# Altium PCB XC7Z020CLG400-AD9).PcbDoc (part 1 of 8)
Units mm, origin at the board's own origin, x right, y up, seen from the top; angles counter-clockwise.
Board outline 38 x 38 mm, 14 copper layers (Top Layer, GND02, ART03, PWR04, ART05, GND06, ART07, ART08, PWR09, ART10, GND11, ART12, PWR13, Bottom Layer); 276 components, 302 nets, 1684 pads, 1576 vias.
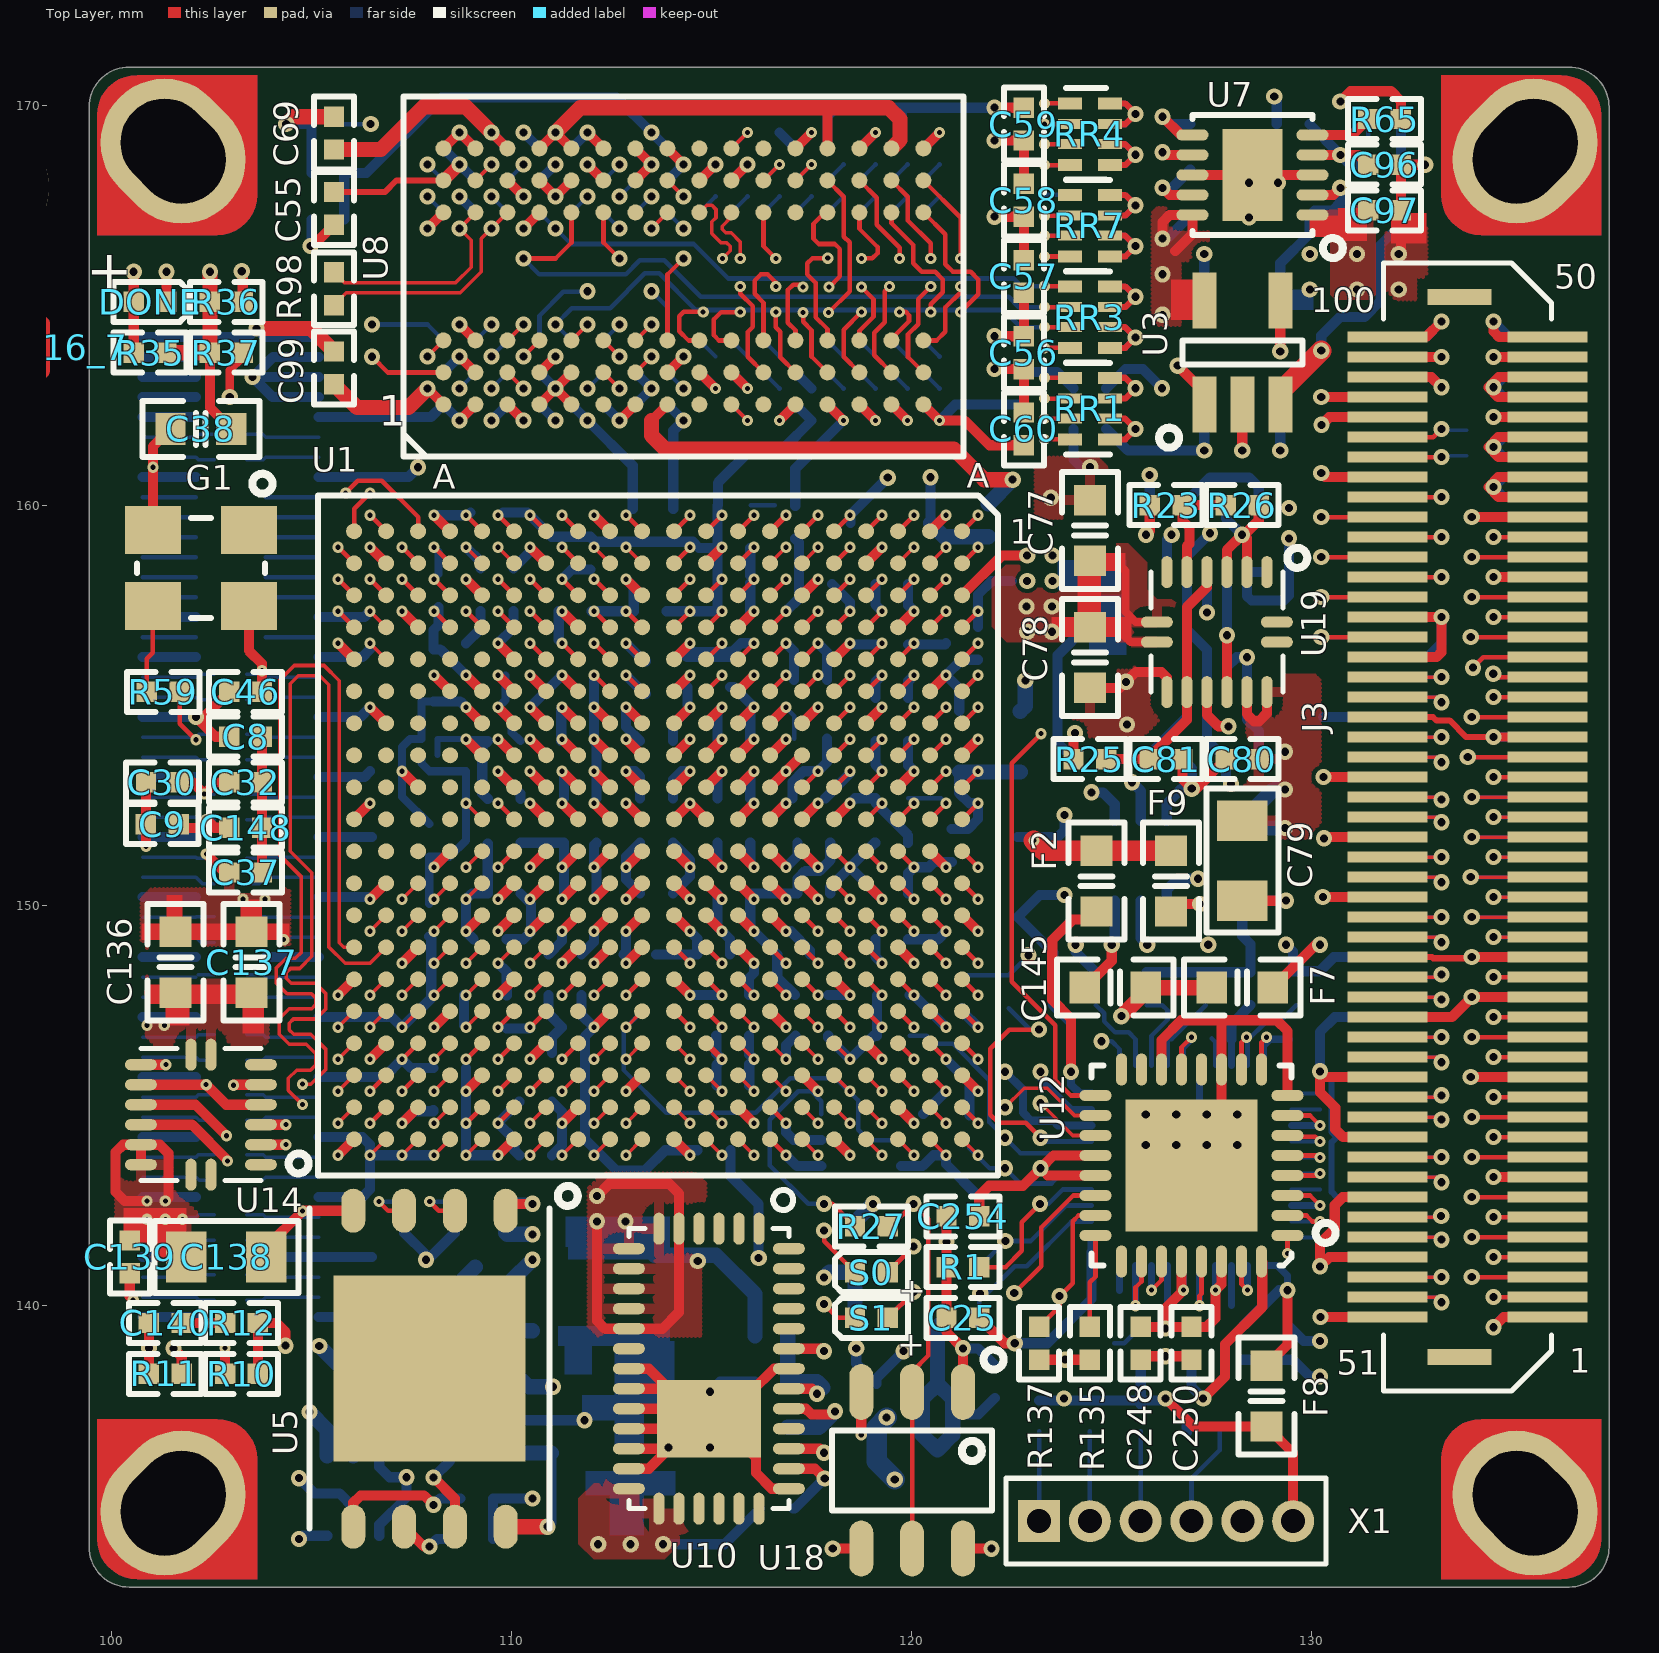
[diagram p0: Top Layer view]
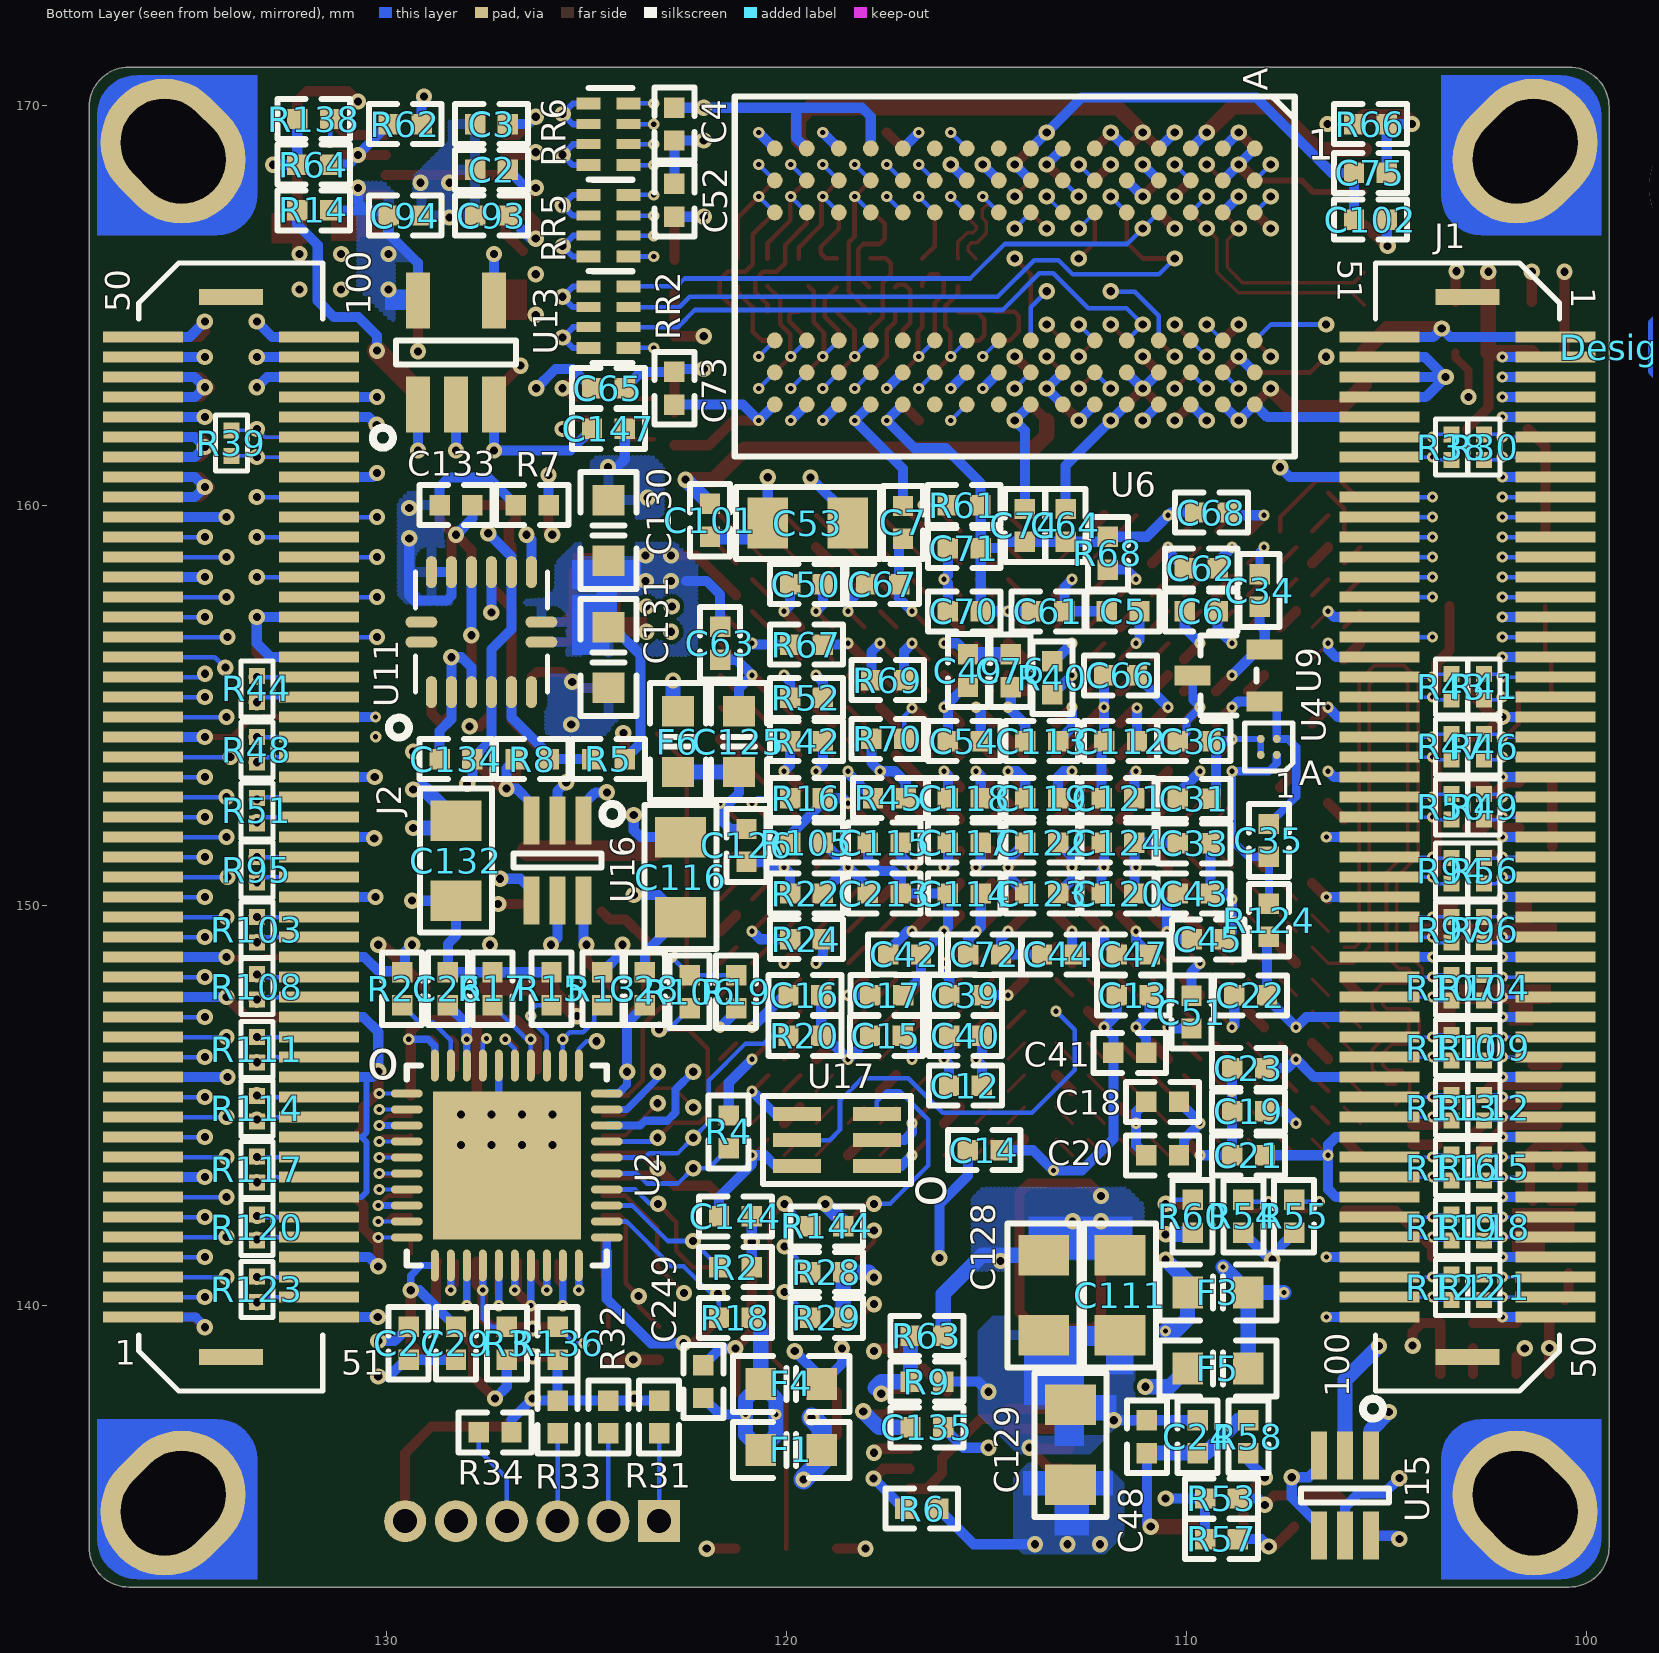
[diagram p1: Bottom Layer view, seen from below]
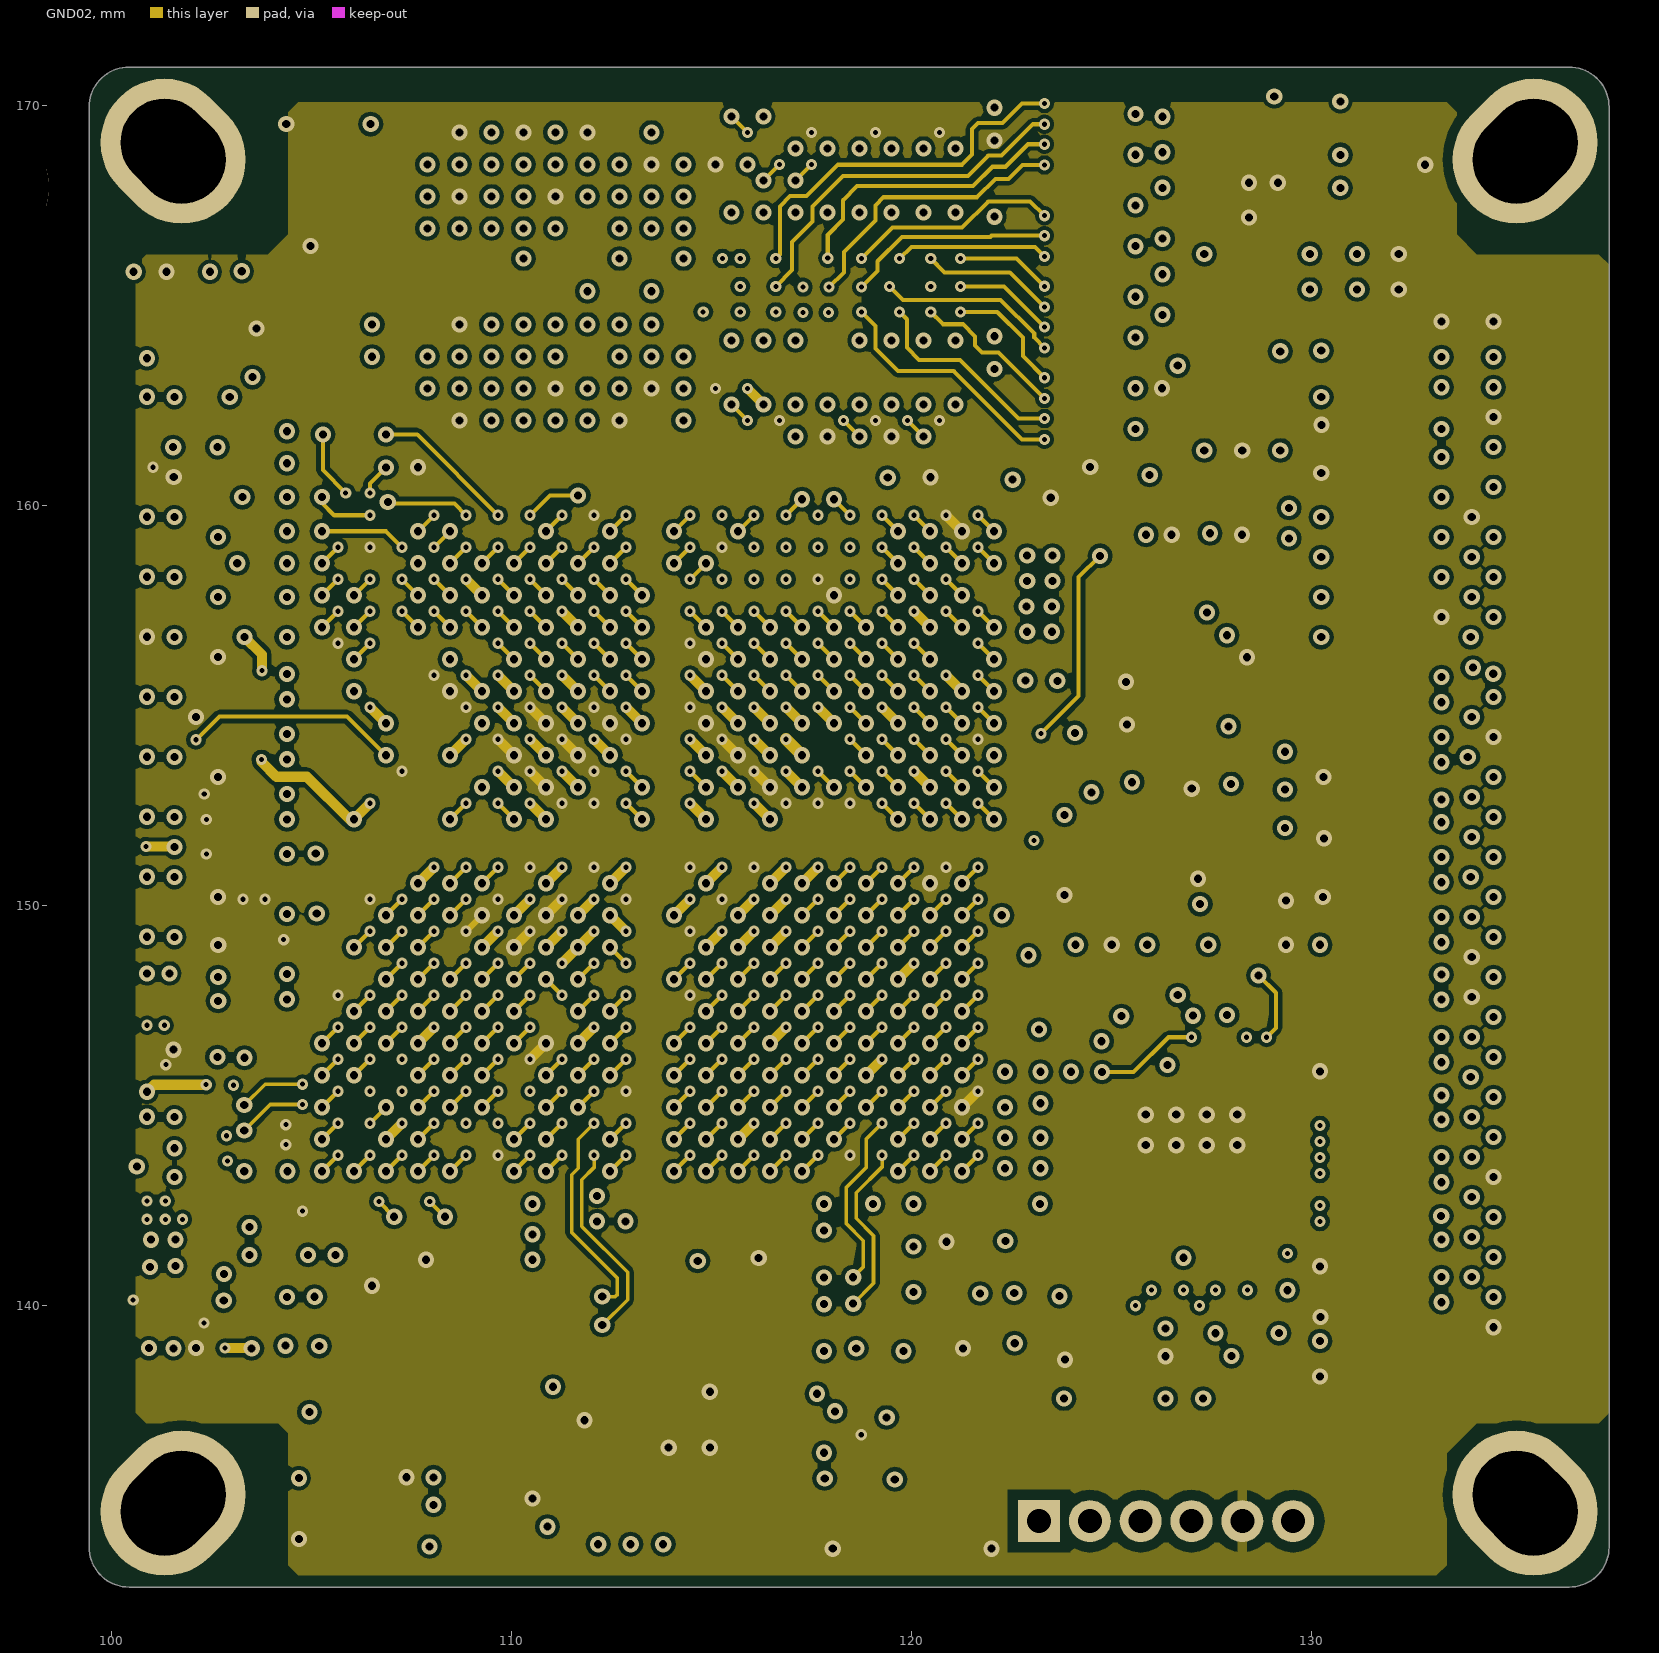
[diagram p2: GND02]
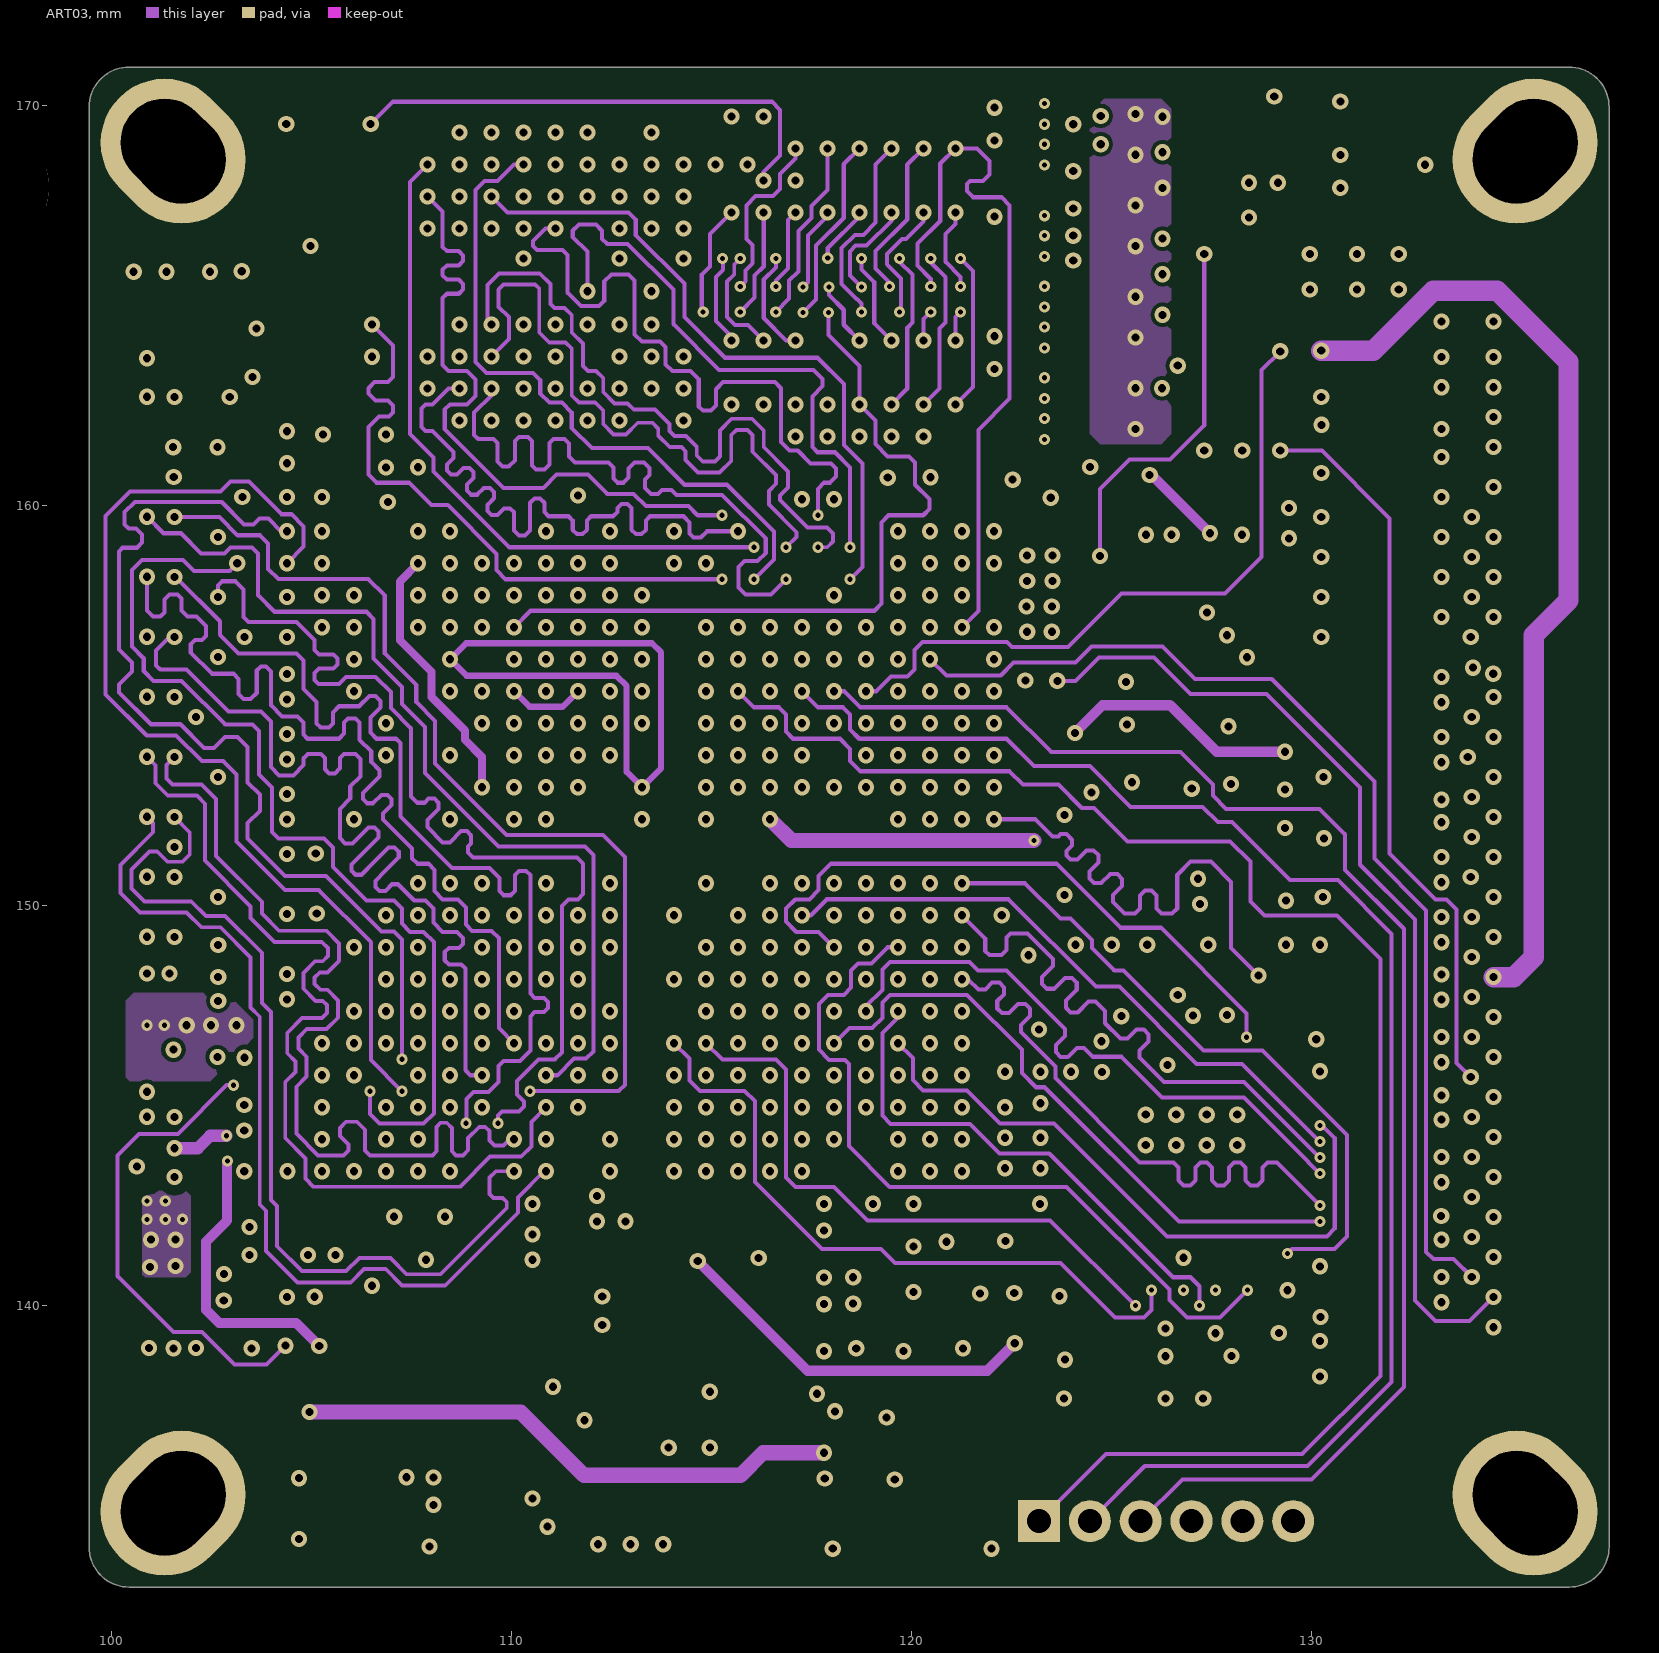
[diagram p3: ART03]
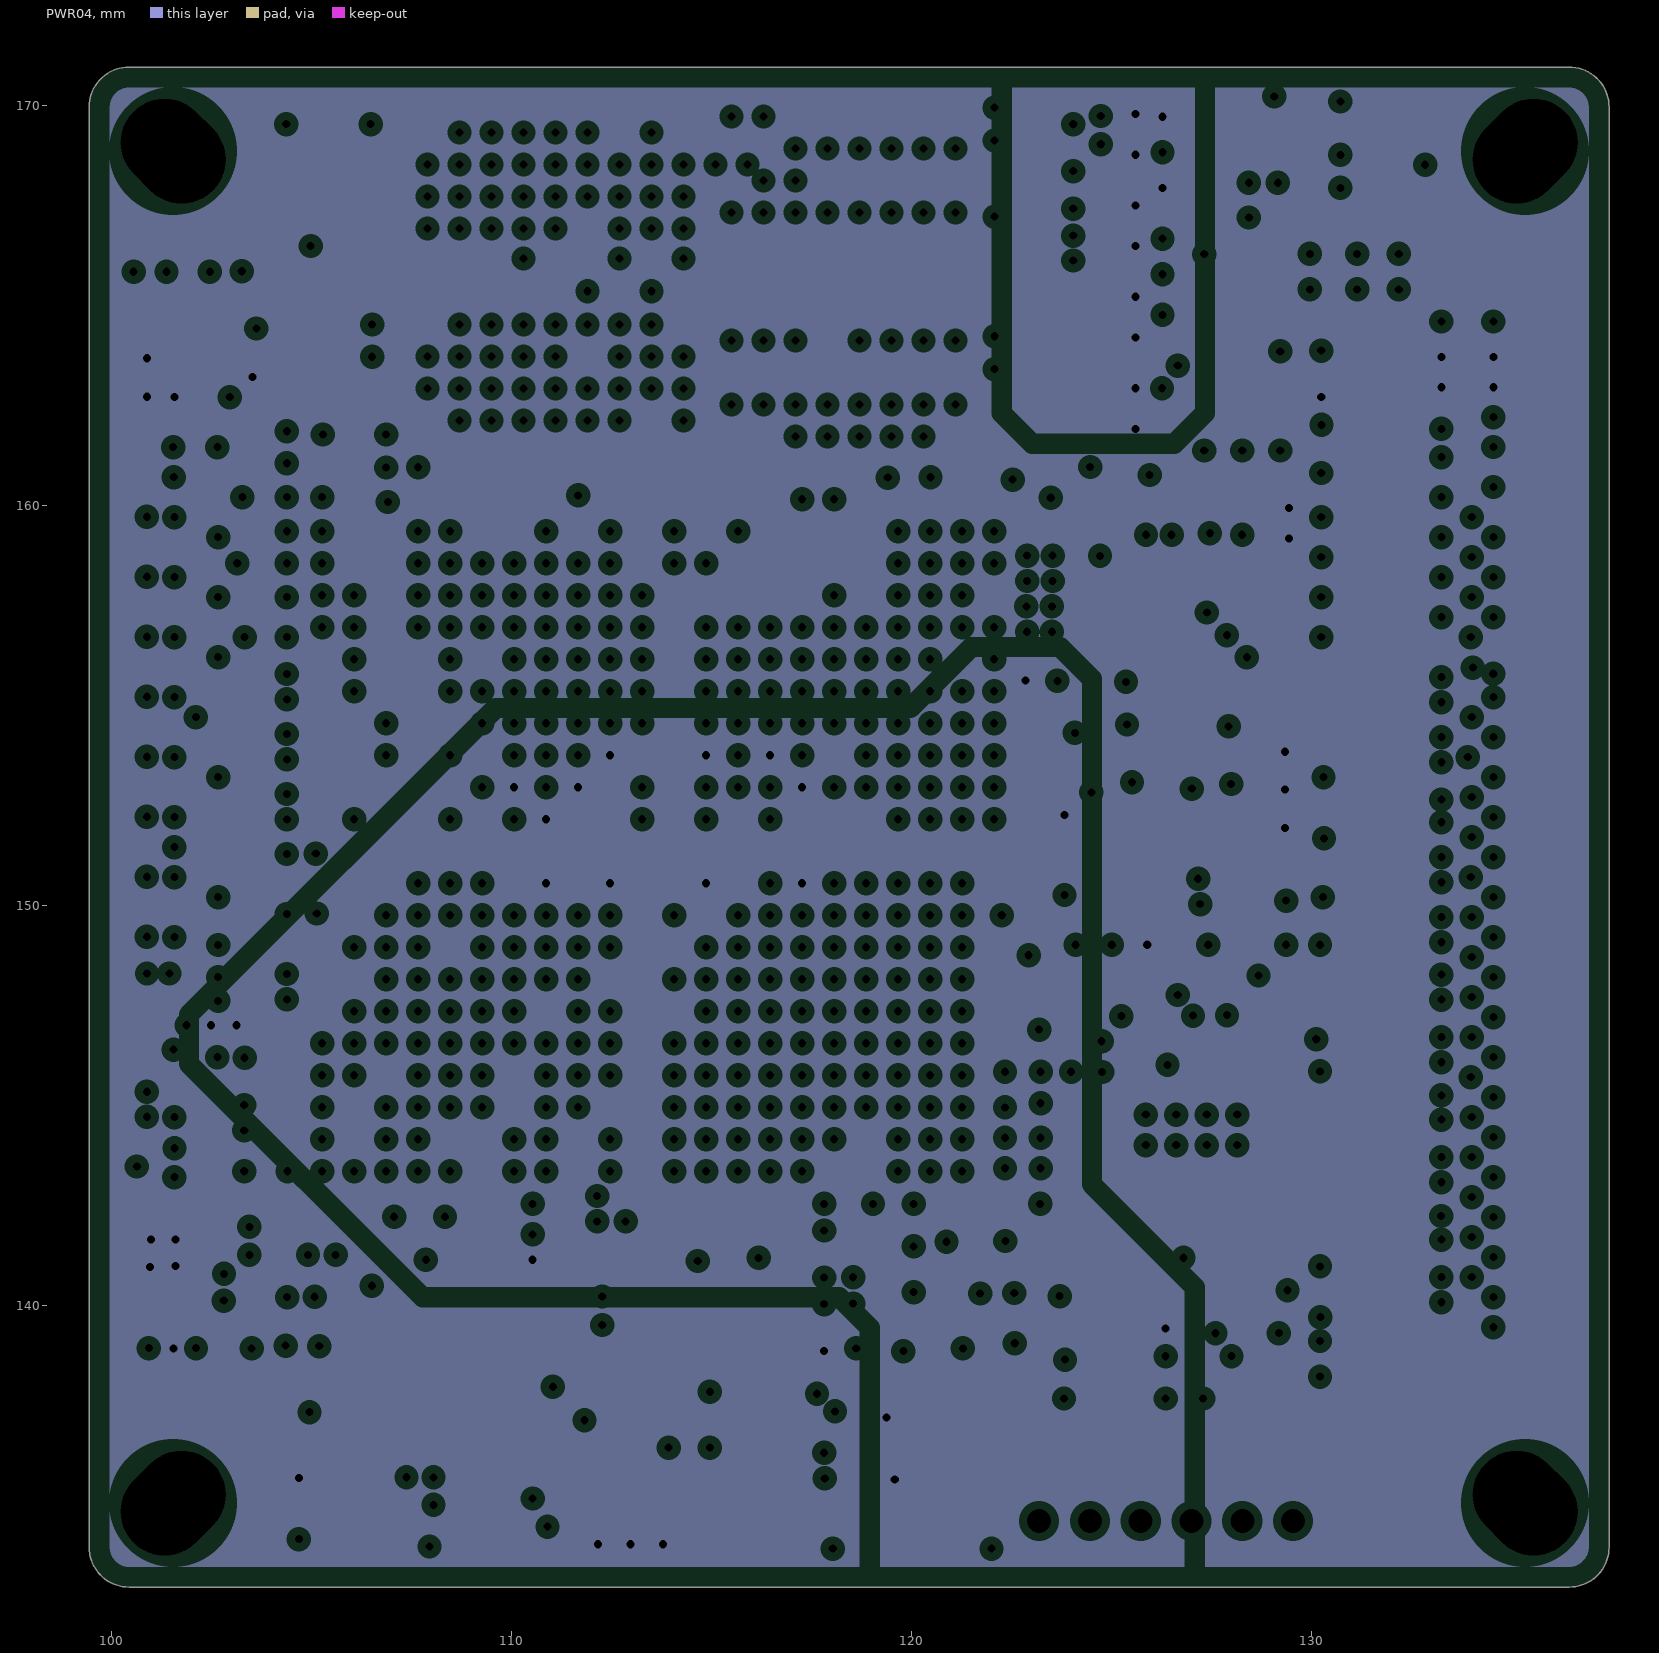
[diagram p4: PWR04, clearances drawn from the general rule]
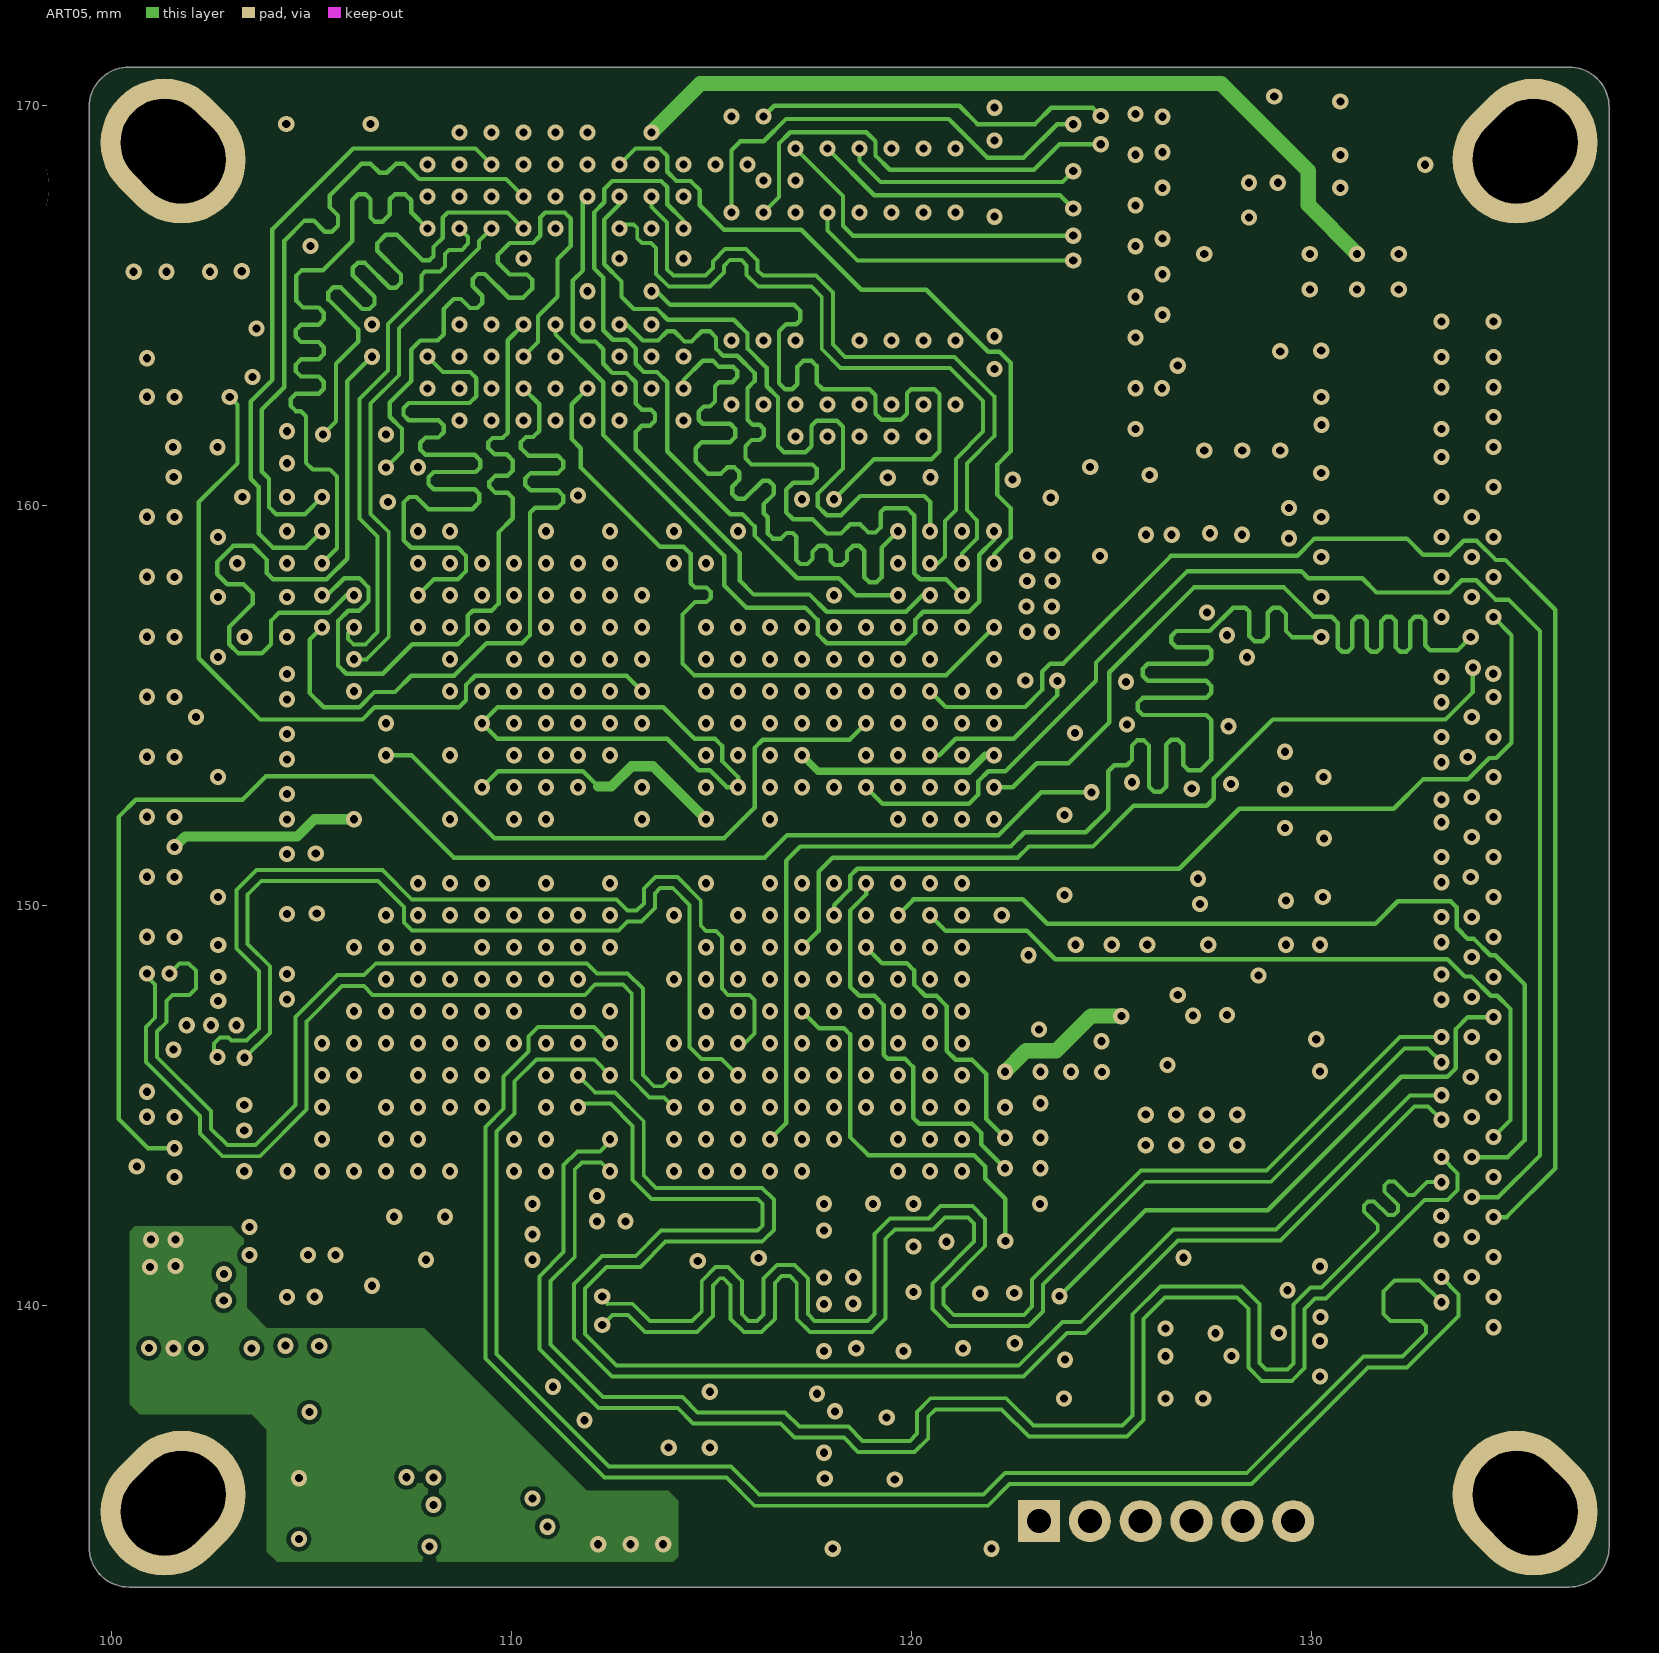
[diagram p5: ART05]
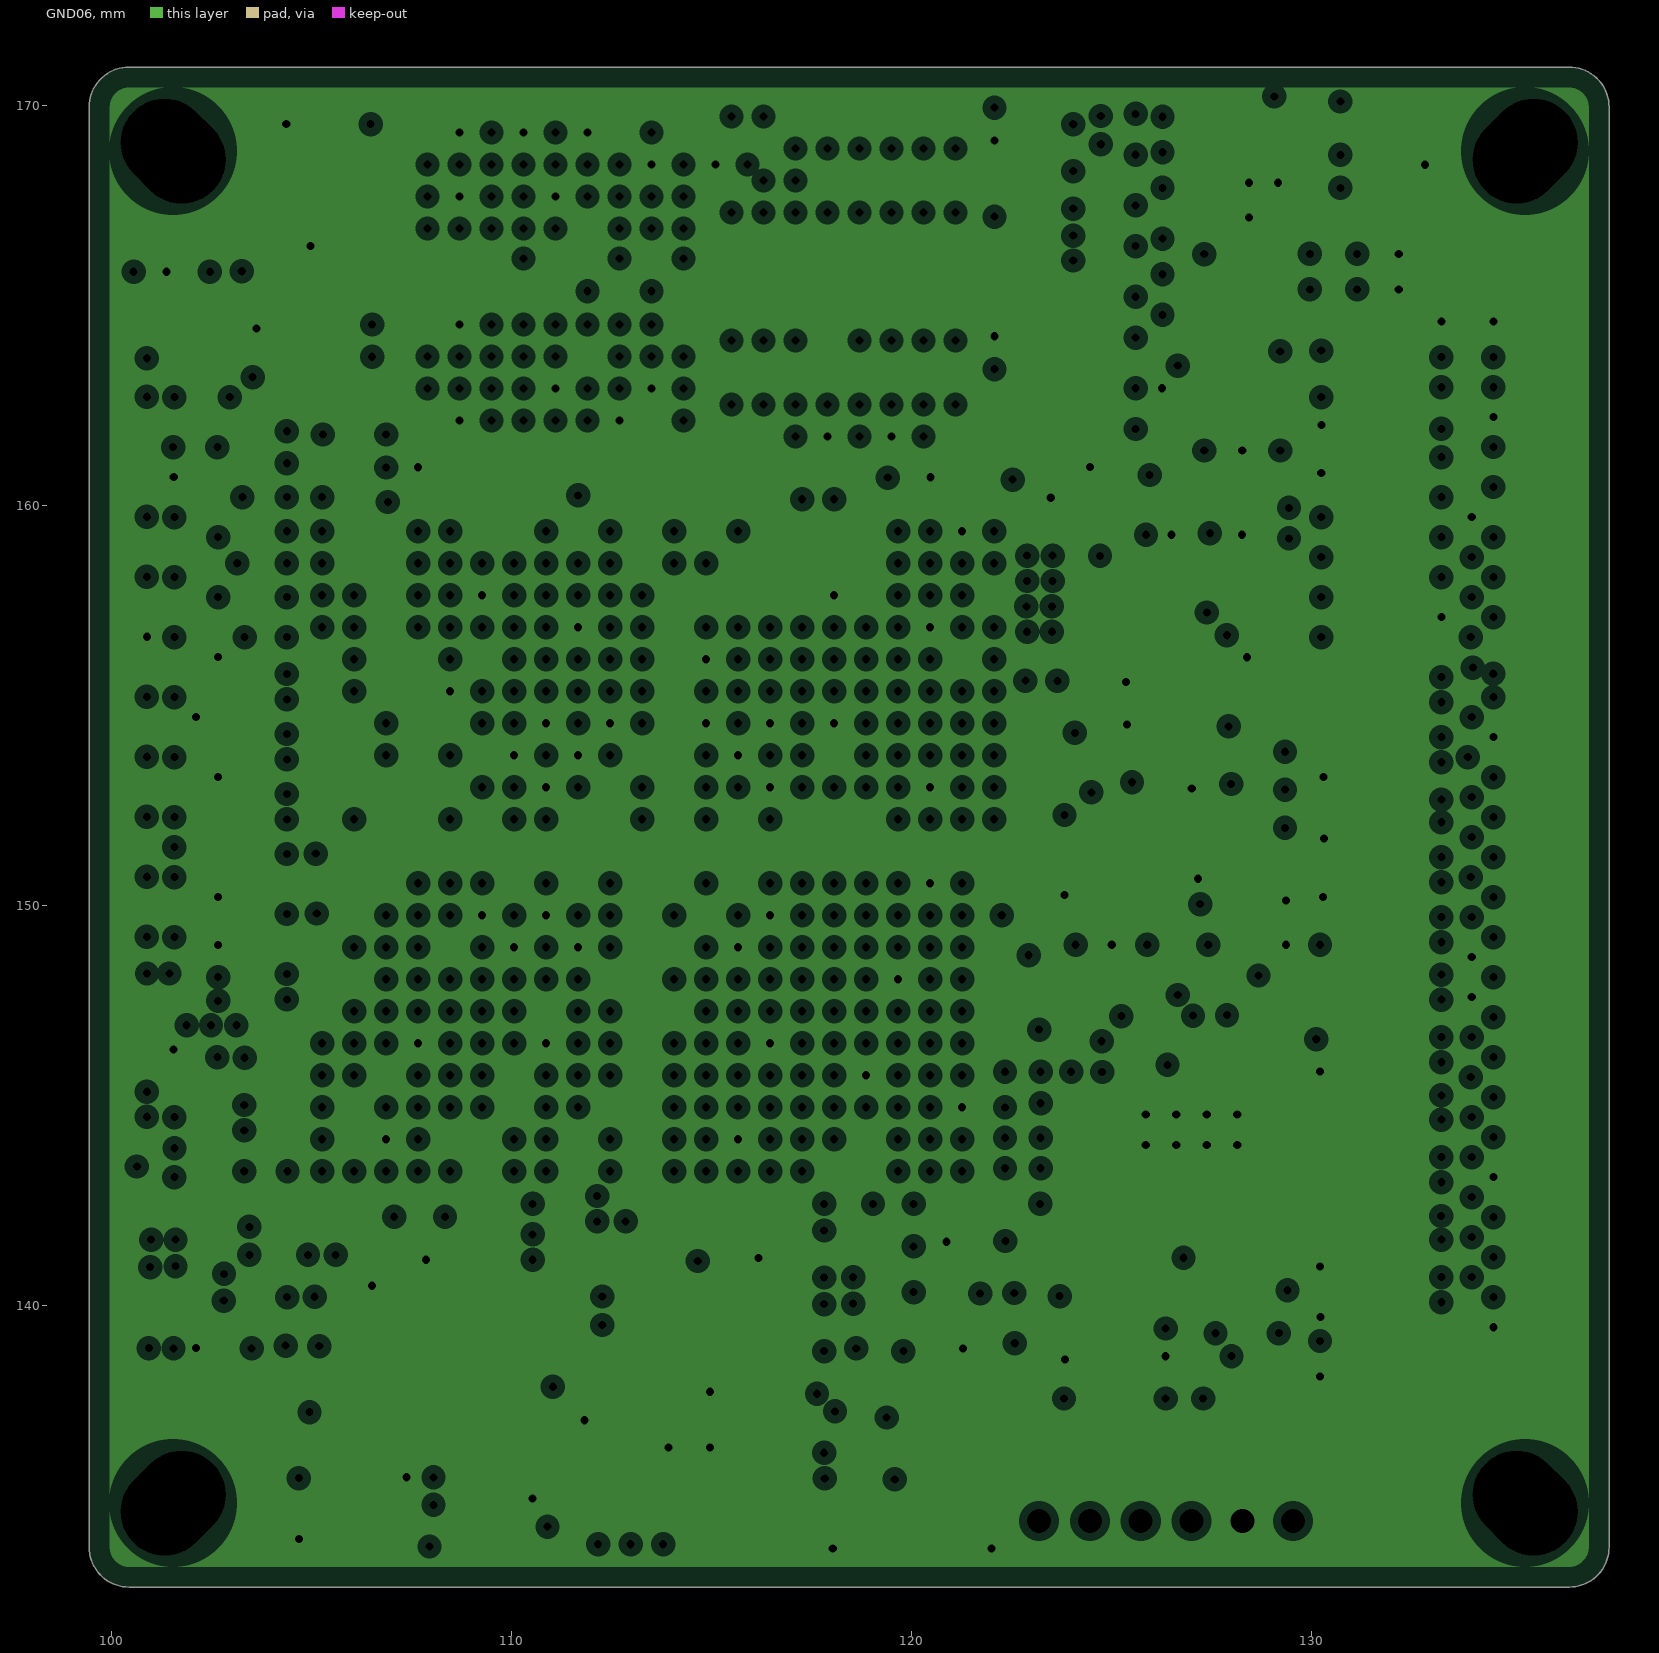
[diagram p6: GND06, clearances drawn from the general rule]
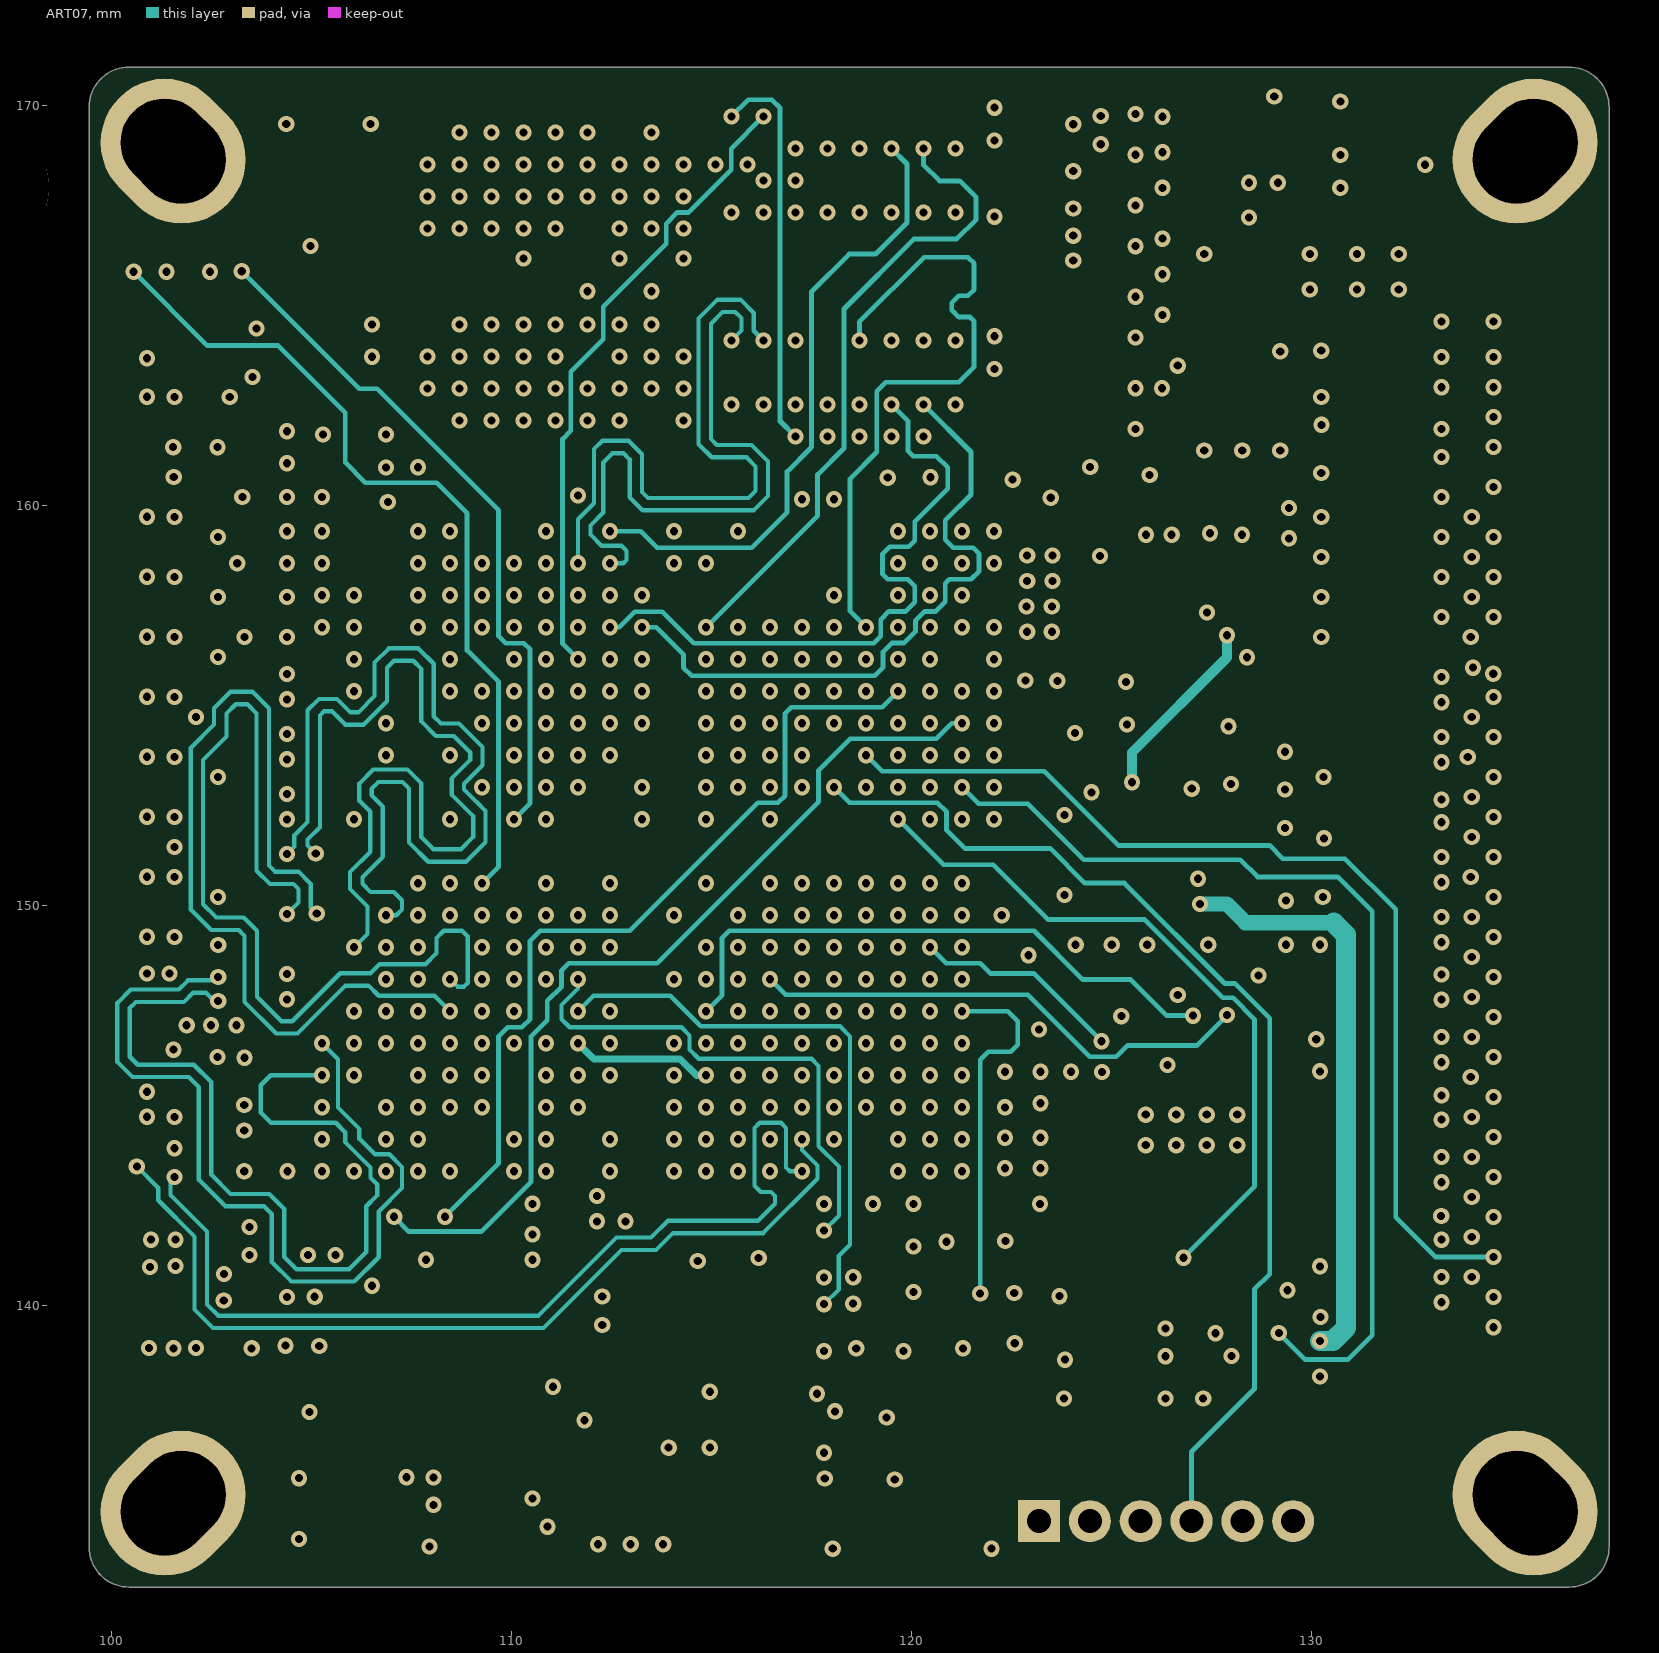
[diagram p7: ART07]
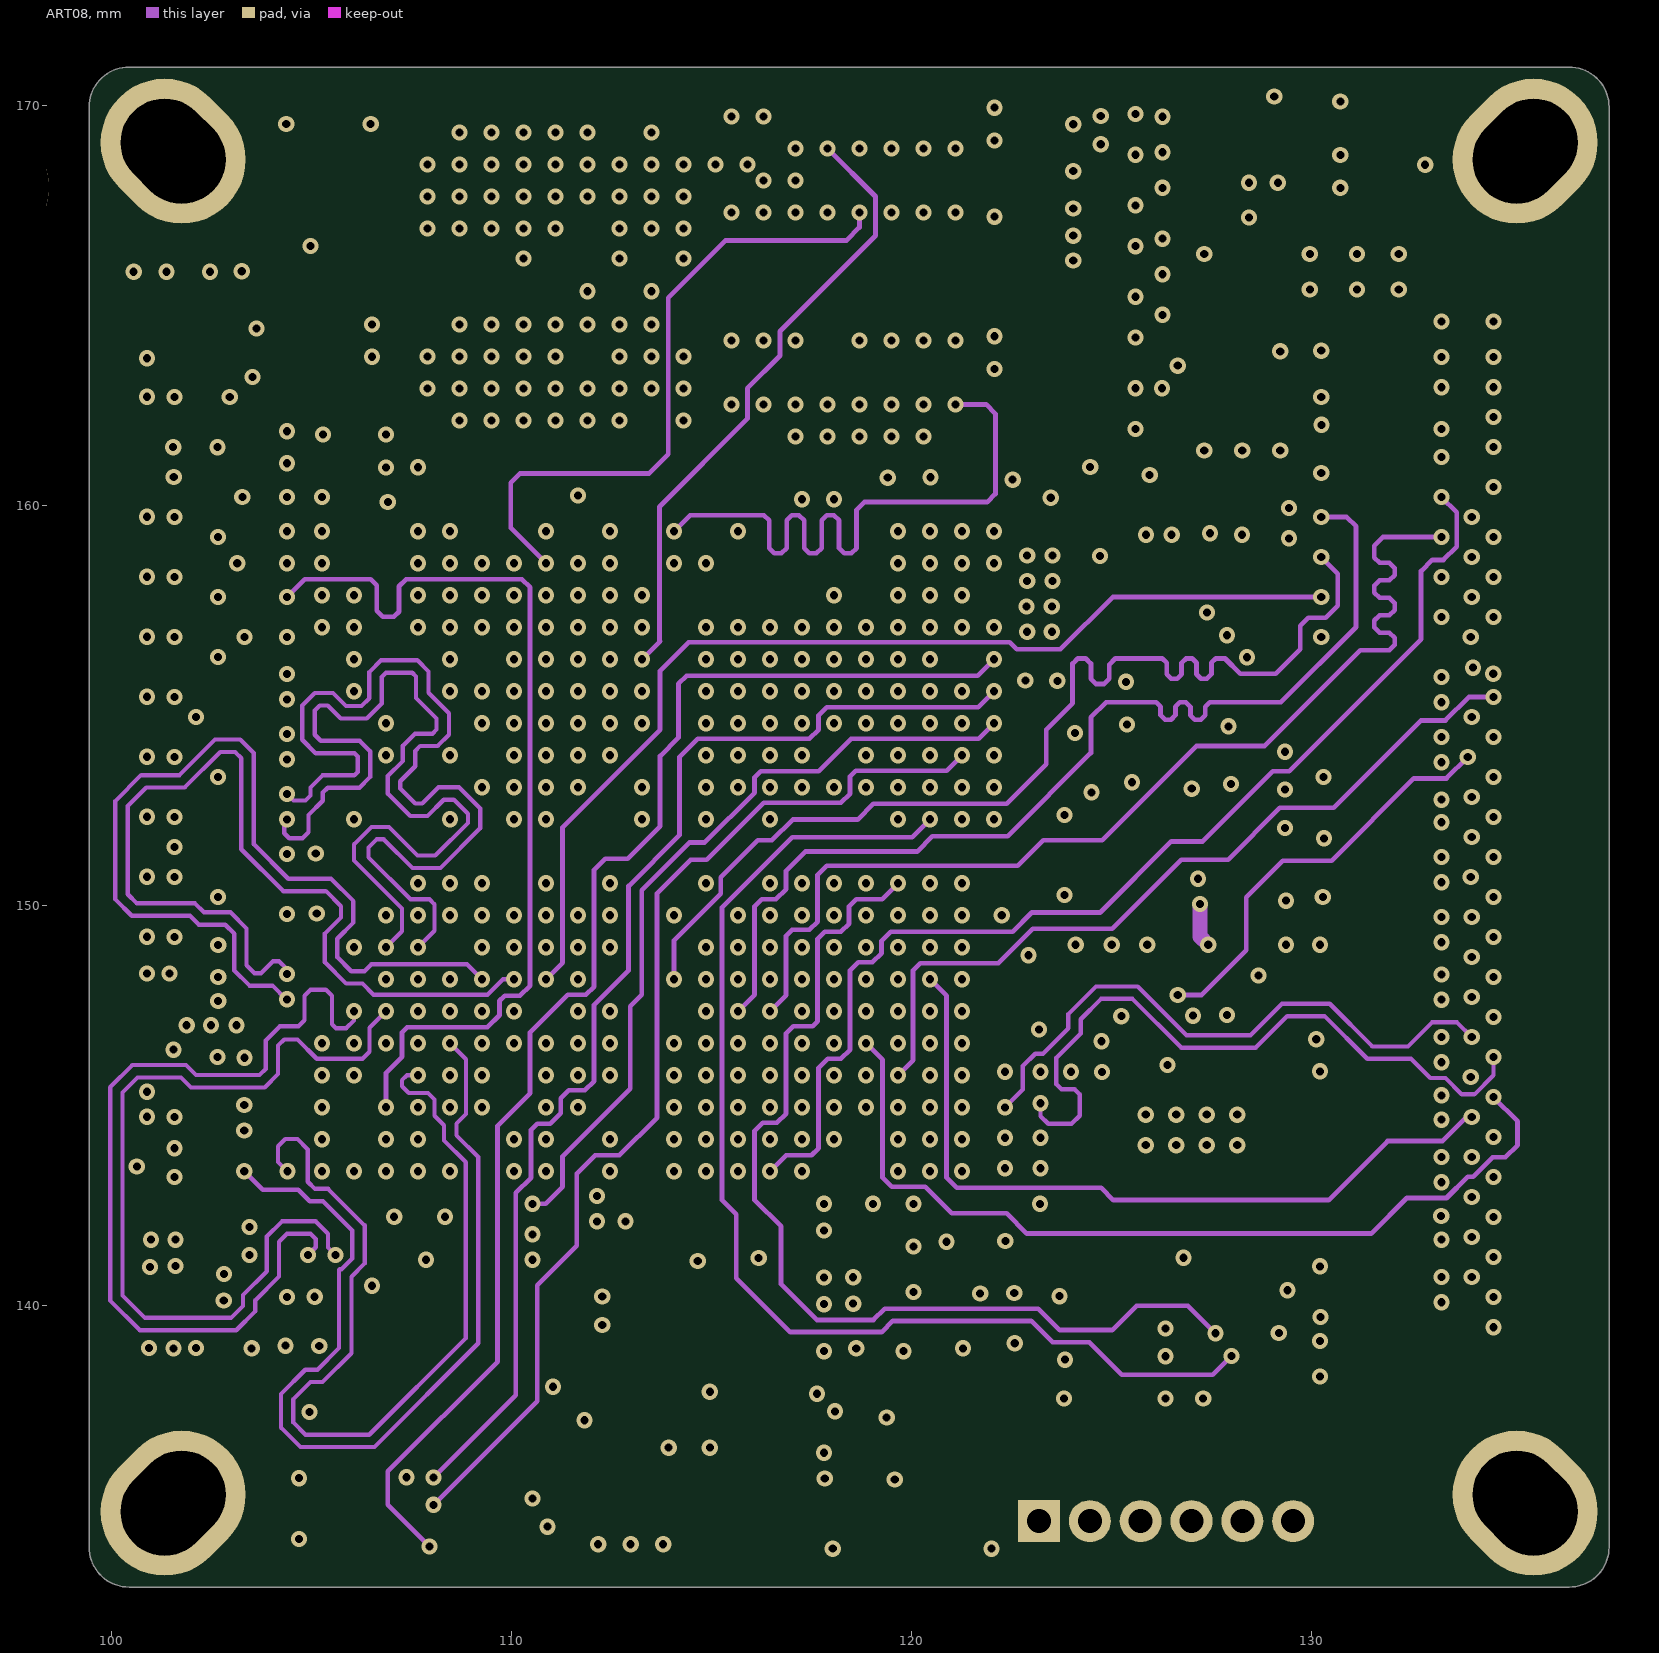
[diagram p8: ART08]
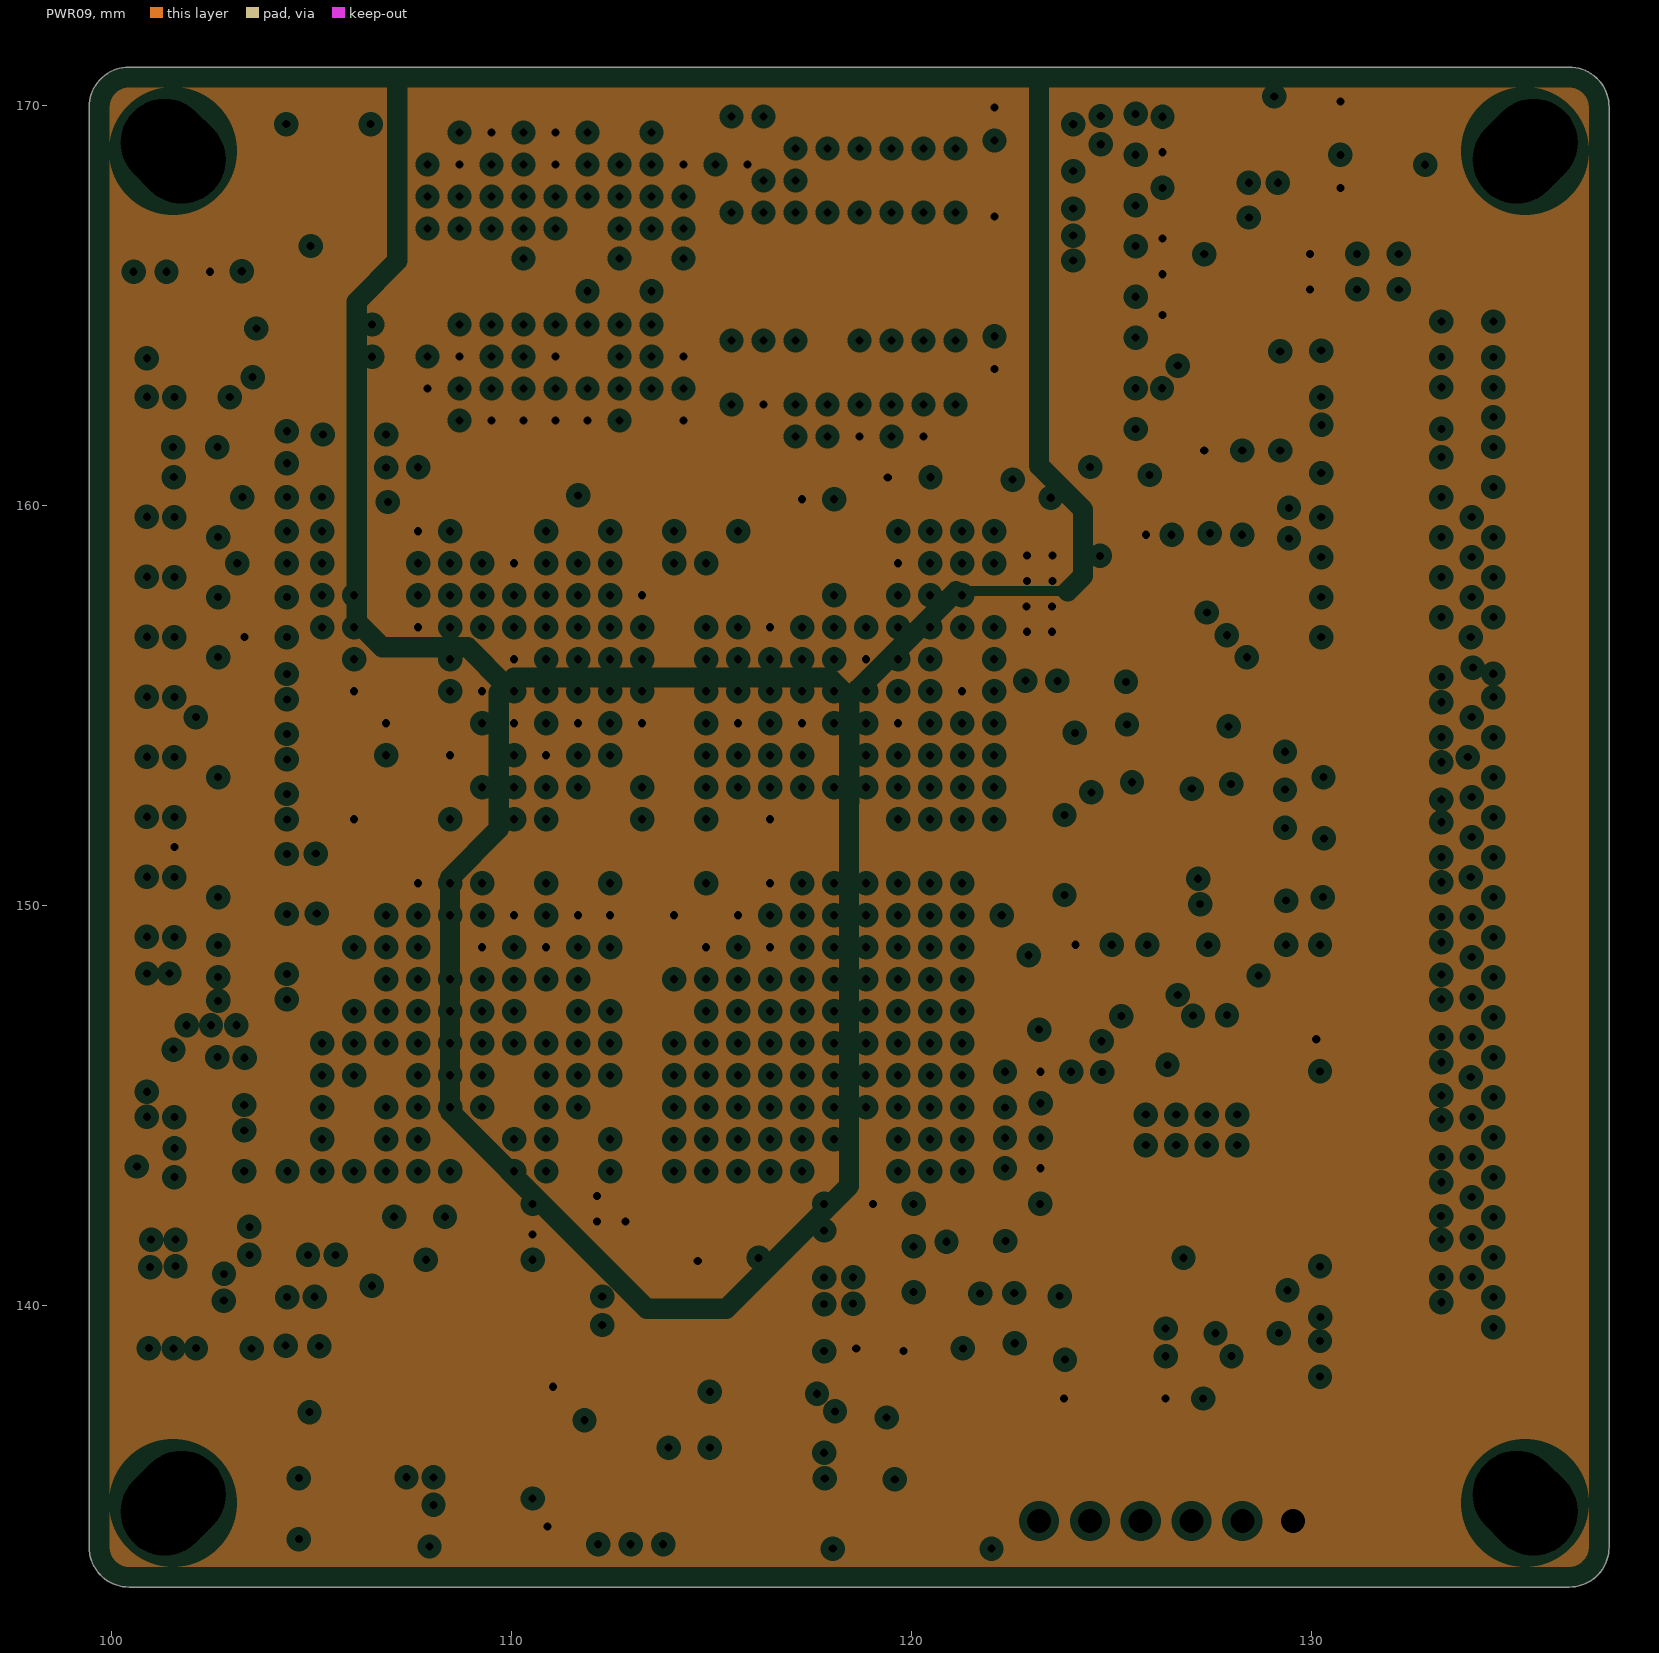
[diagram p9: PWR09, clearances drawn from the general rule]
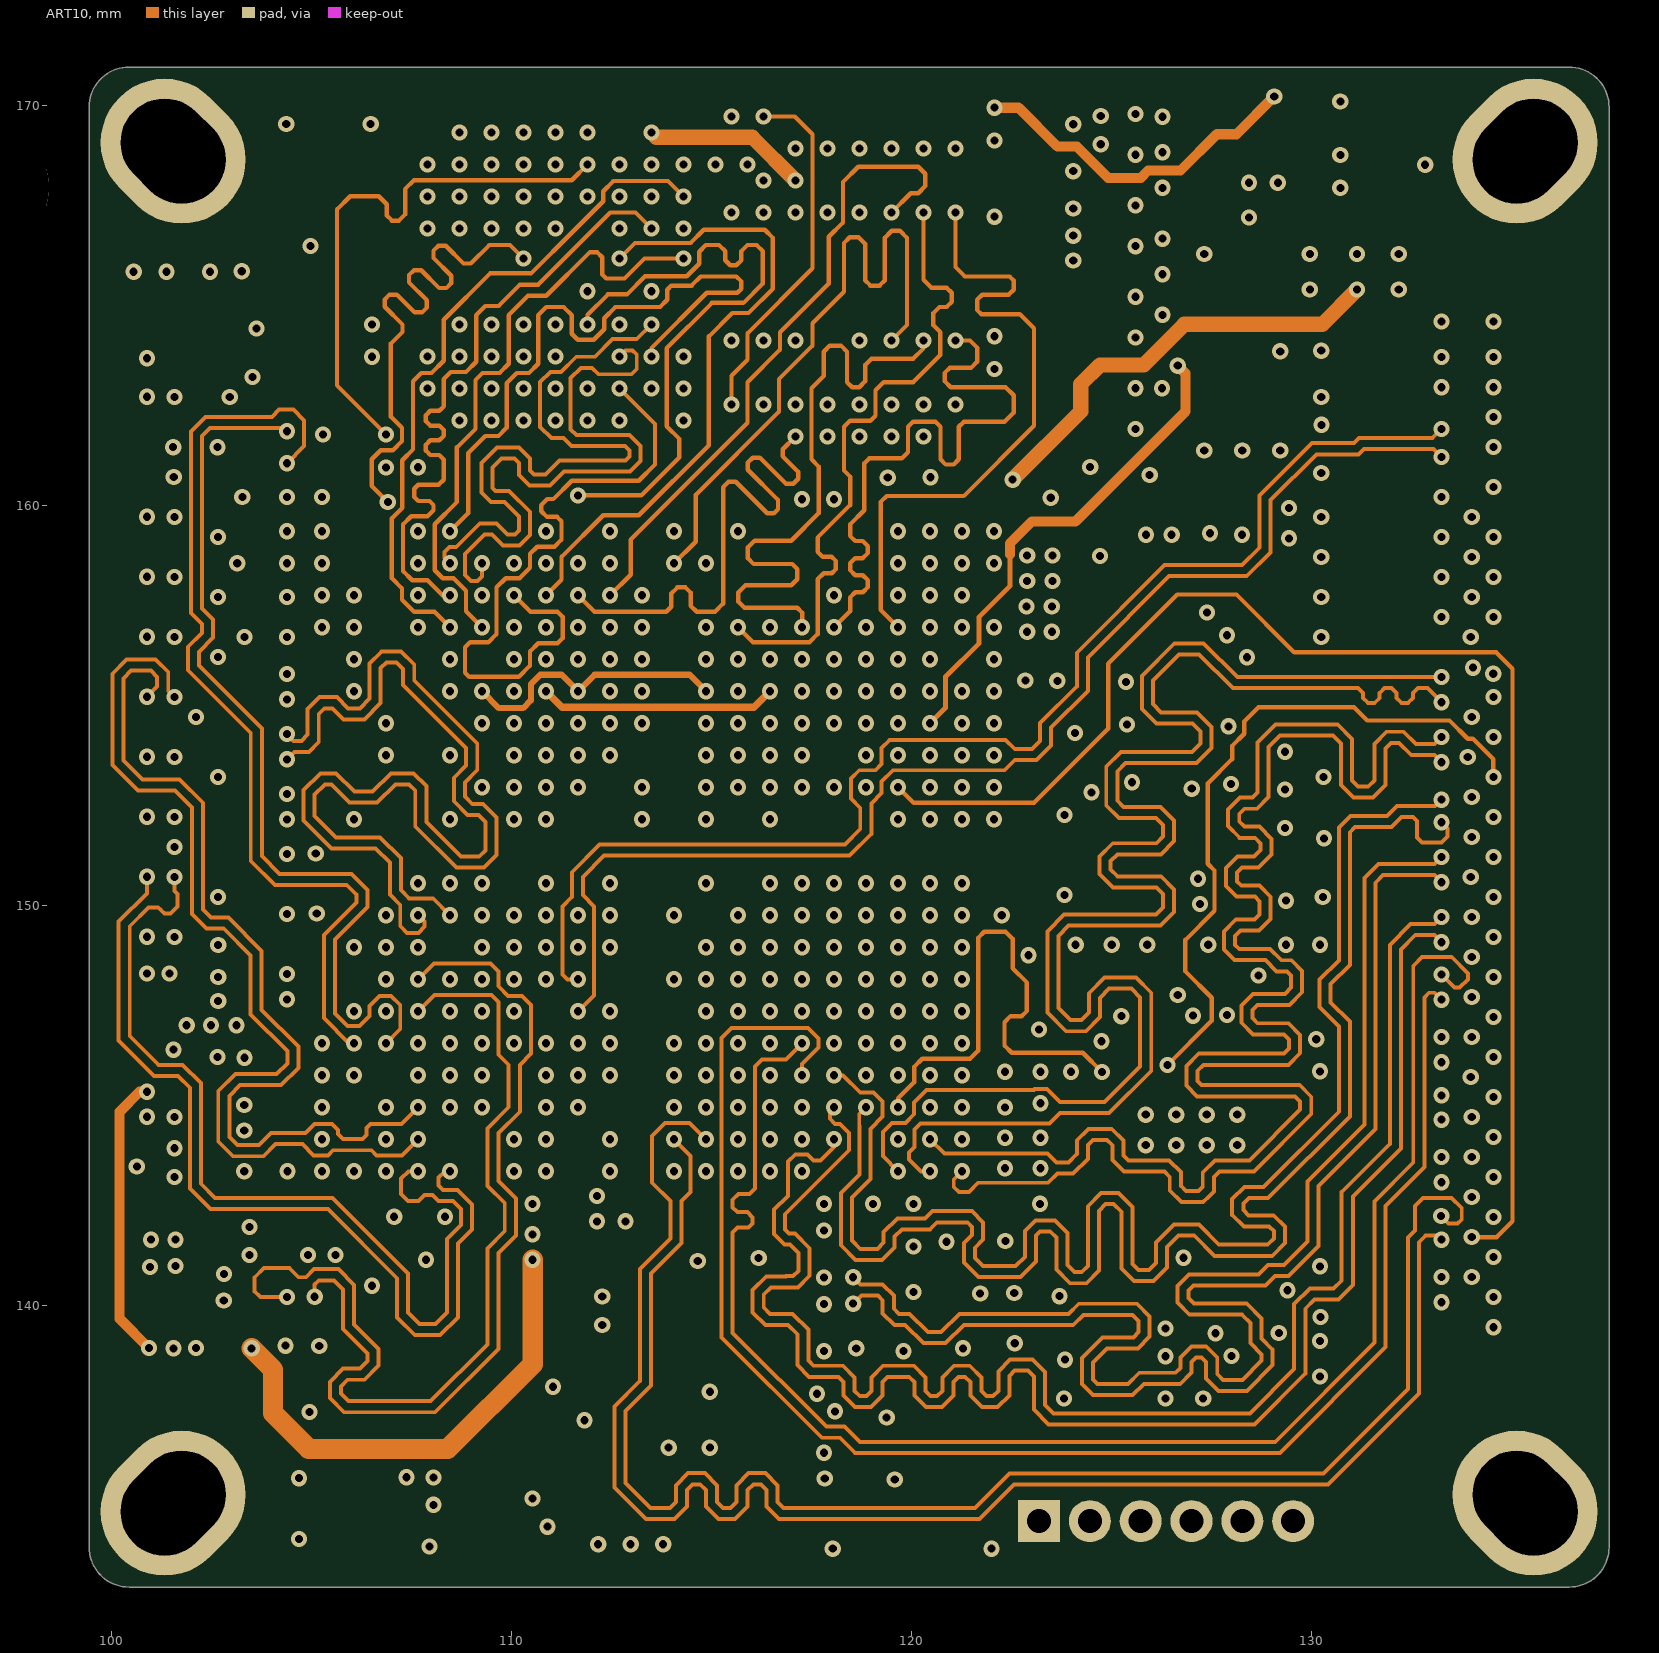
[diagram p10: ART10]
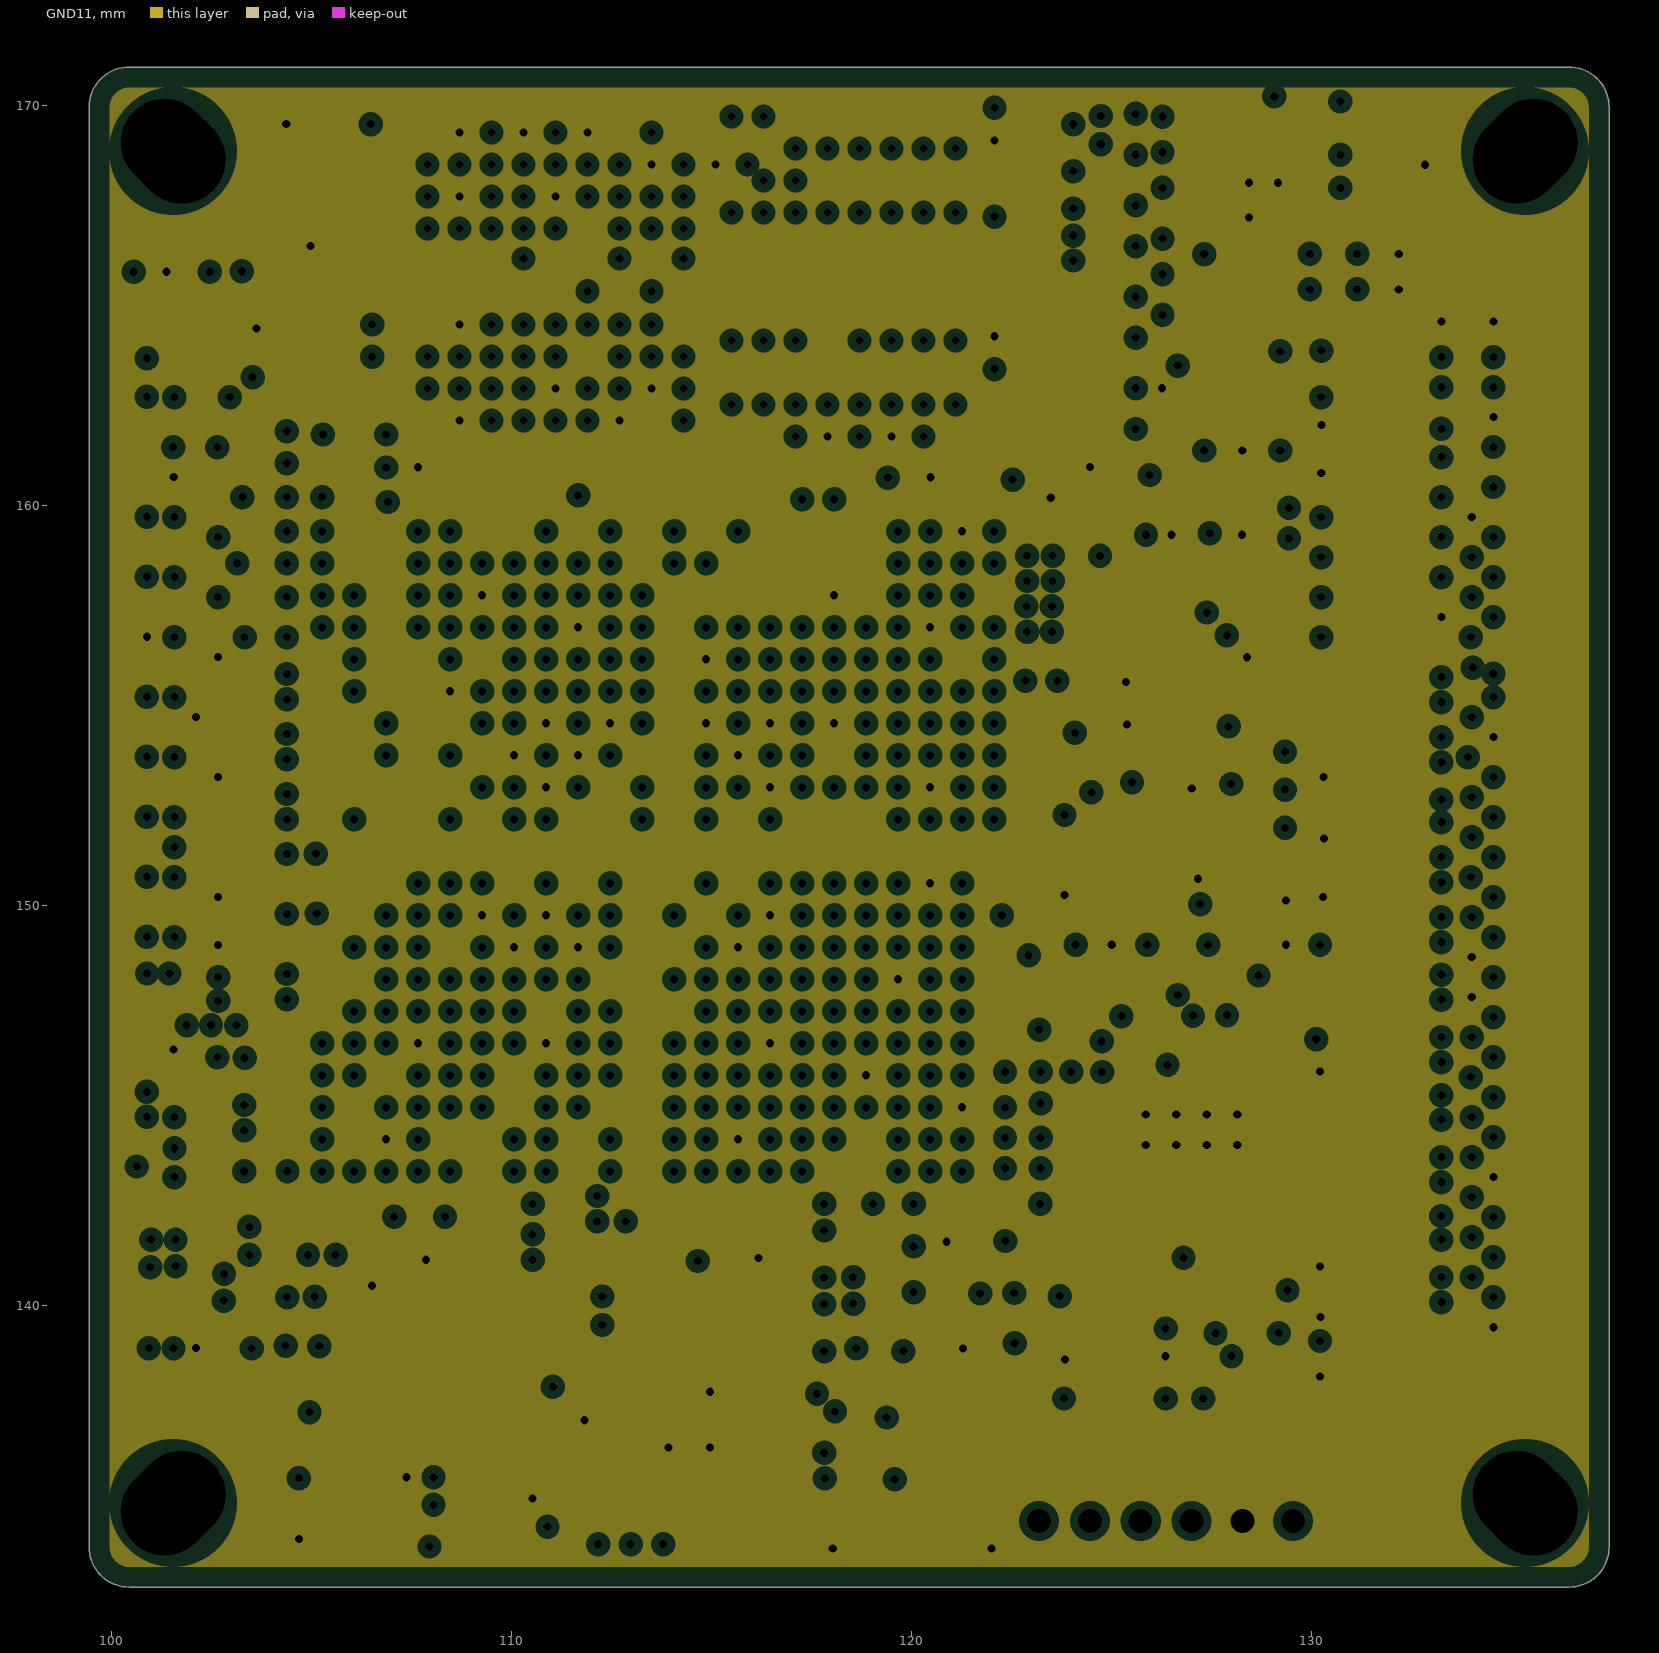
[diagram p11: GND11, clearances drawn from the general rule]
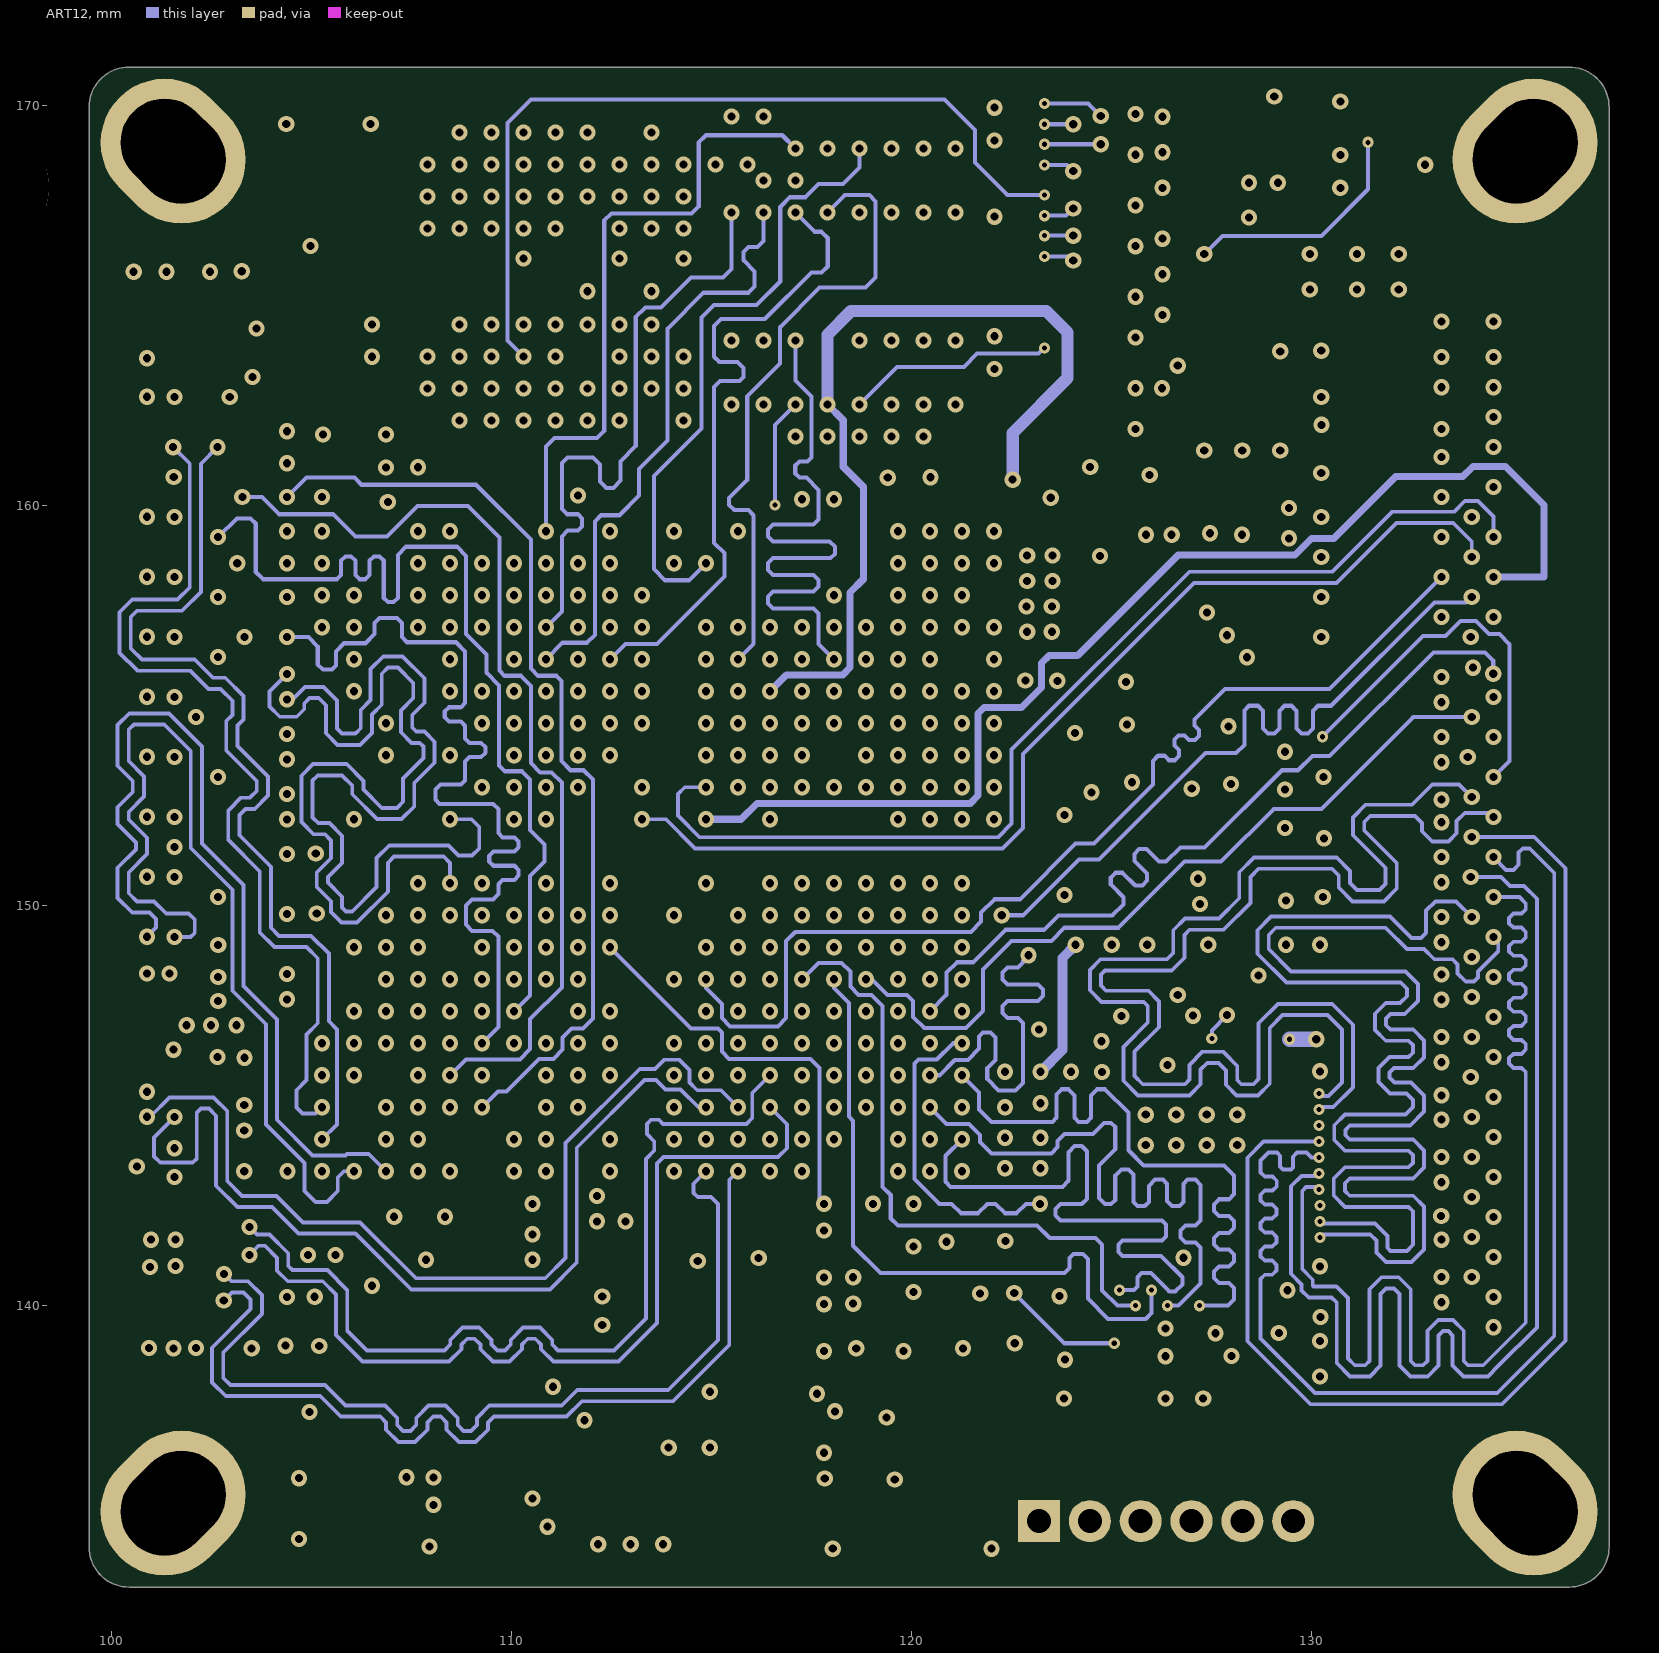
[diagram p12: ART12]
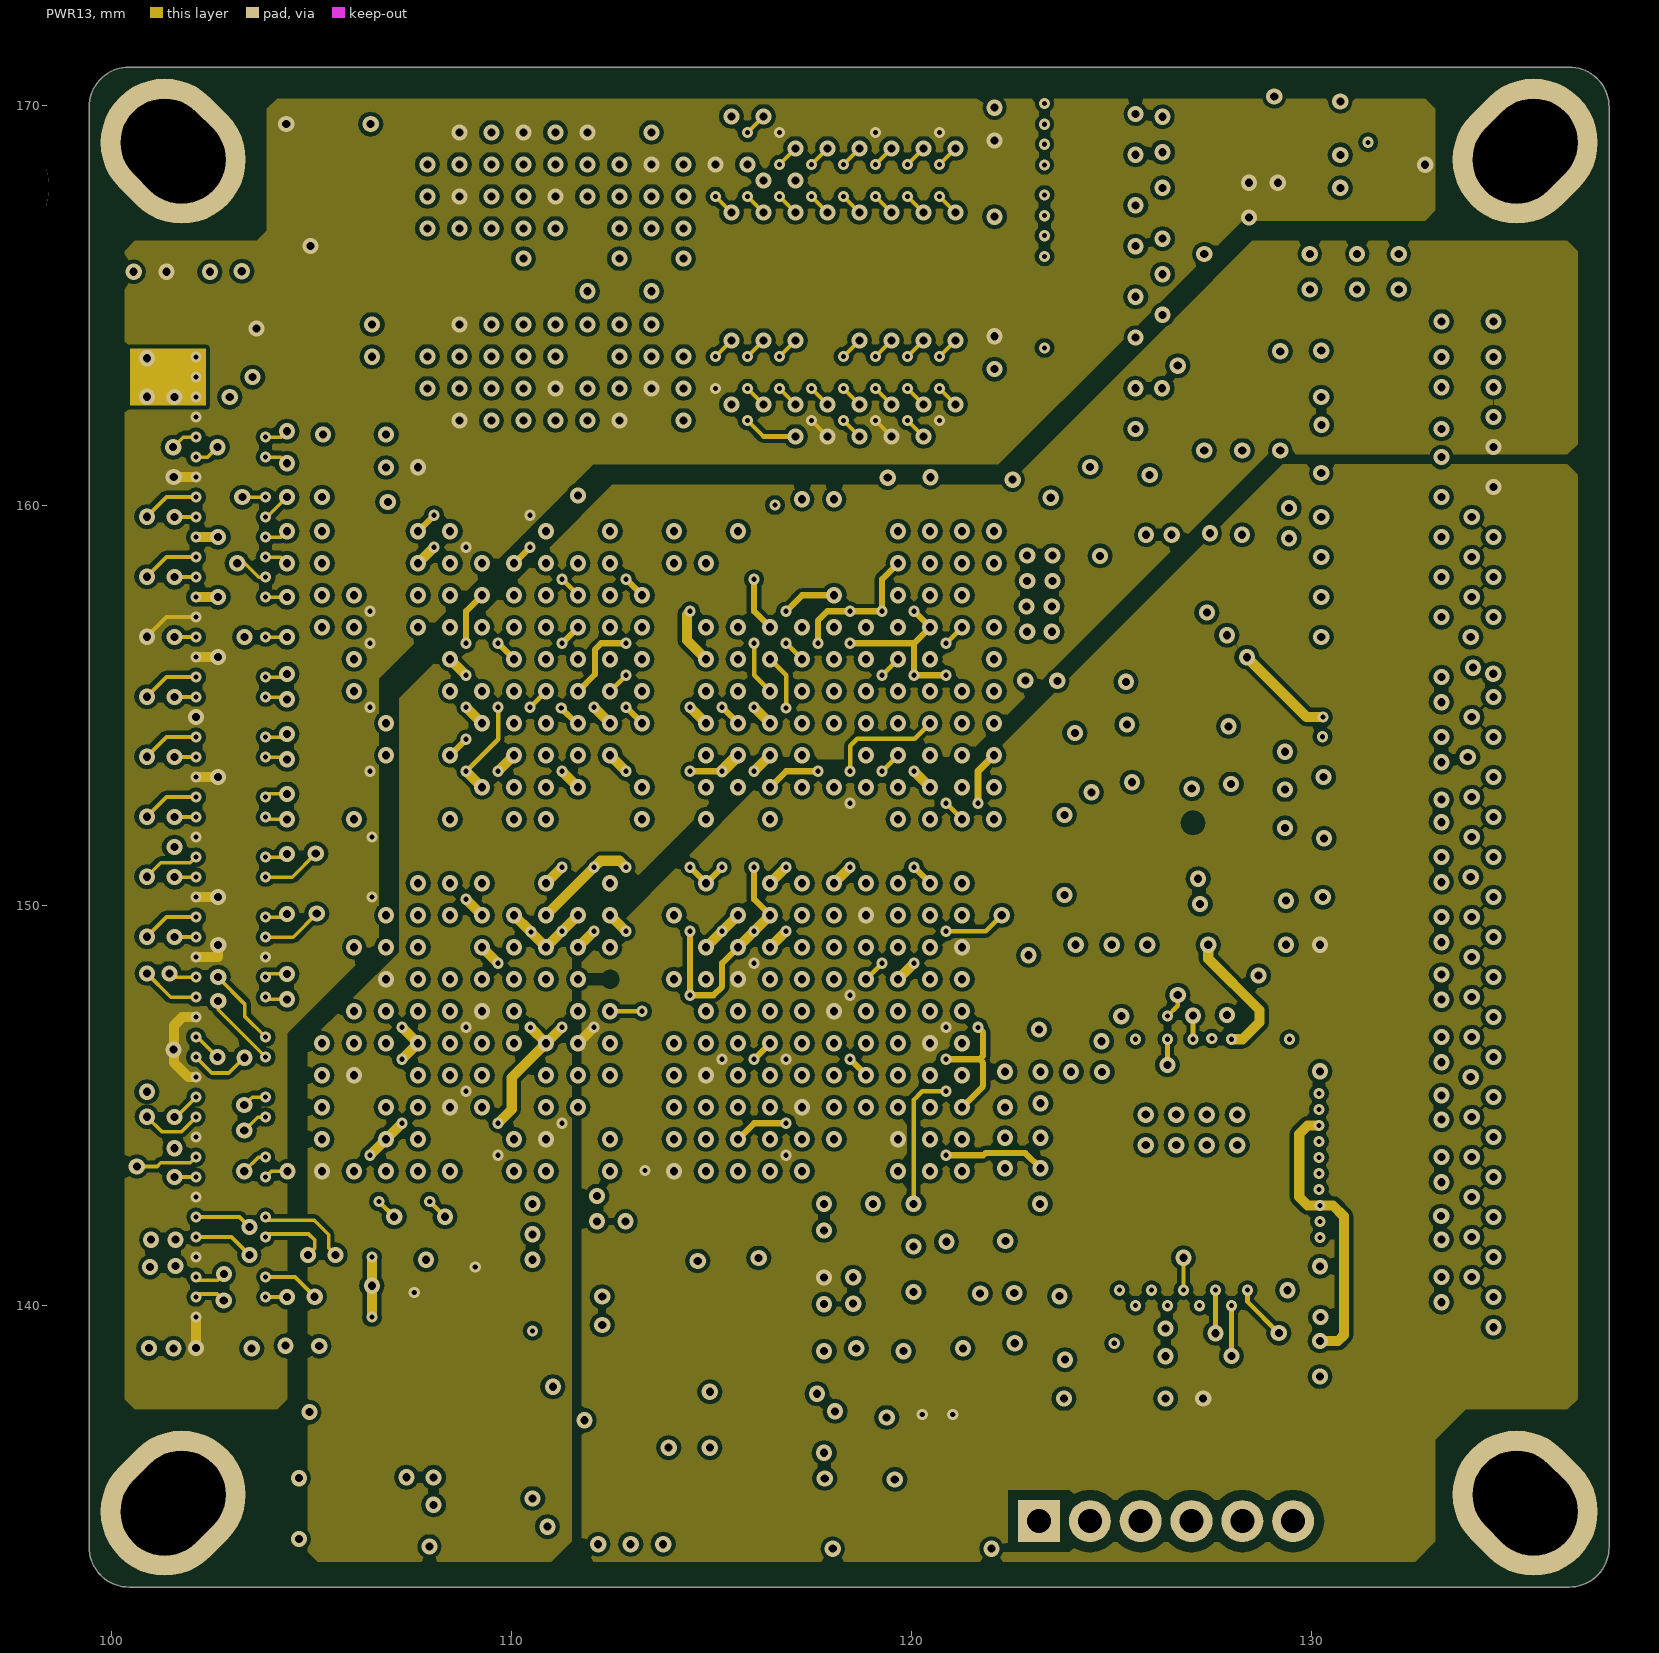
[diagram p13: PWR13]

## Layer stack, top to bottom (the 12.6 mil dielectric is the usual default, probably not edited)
Top Layer: signal copper 0.0356
Dielectric: core 0.32, FR-4, Dk 4.8
GND02: signal copper 0.0356
Dielectric: prepreg 0.32, FR-4, Dk 4.8
ART03: signal copper 0.0356
Dielectric: core 0.32, FR-4, Dk 4.8
PWR04: plane copper 0.0356, net (Multiple Nets)
Dielectric: prepreg 0.32, FR-4, Dk 4.8
ART05: signal copper 0.0356
Dielectric: core 0.32, FR-4, Dk 4.8
GND06: plane copper 0.0356, net GND
Dielectric: prepreg 0.32, FR-4, Dk 4.8
ART07: signal copper 0.0356
Dielectric: core 0.32, FR-4, Dk 4.8
ART08: signal copper 0.0356
Dielectric: prepreg 0.32, FR-4, Dk 4.8
PWR09: plane copper 0.0356, net (Multiple Nets)
Dielectric: core 0.32, FR-4, Dk 4.8
ART10: signal copper 0.0356
Dielectric: prepreg 0.32, FR-4, Dk 4.8
GND11: plane copper 0.0356, net GND
Dielectric: core 0.32, FR-4, Dk 4.8
ART12: signal copper 0.0356
Dielectric: prepreg 0.32, FR-4, Dk 4.8
PWR13: signal copper 0.0356
Dielectric: core 0.32, FR-4, Dk 4.8
Bottom Layer: signal copper 0.0356

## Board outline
99.441,133.969 99.441,169.969 cw(c100.441,169.969) 100.441,170.969 136.441,170.969 cw(c136.441,169.969) 137.441,169.969 137.441,133.969 cw(c136.441,133.969) 136.441,132.969 100.441,132.969 cw(c100.441,133.969)

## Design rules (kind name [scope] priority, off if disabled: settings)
Clearance Clearance_poly [inpoly vs ispad] p1: gap=0.254
Clearance [All] p2: gap=0.102
DiffPairsRouting 90 [(InDifferentialPairClass('90'))] p1 off: maxlimit=0.168 minlimit=0.168 mostfreqgap=0.168 maxuncoupledlength=12.7
DiffPairsRouting [All] p2: maxlimit=0.254 minlimit=0.168 mostfreqgap=0.203 toplayer_maxgap=0.168 toplayer_prefgap=0.168 midlayer1_mingap=0.183 midlayer1_maxgap=0.183 midlayer1_prefgap=0.183 midlayer2_mingap=0.178 midlayer2_maxgap=0.178 midlayer2_prefgap=0.178 midlayer3_mingap=0.178 midlayer3_maxgap=0.178 midlayer3_prefgap=0.178 midlayer4_mingap=0.183 midlayer4_maxgap=0.183 midlayer4_prefgap=0.183 midlayer5_mingap=0.254 midlayer5_prefgap=0.254 midlayer6_mingap=0.203 midlayer6_maxgap=0.203 midlayer7_mingap=0.203 midlayer7_maxgap=0.203 midlayer11_mingap=0.254 midlayer11_prefgap=0.254 bottomlayer_maxgap=0.168 bottomlayer_prefgap=0.168 maxuncoupledlength=12.7
PlaneClearance [All] p1: clearance=0.203
PlaneConnect PlaneConnect_via [isvia] p1: planeconnectstyle=Direct reliefexpansion=0.508 reliefentries=4 reliefconductorwidth=0.254 reliefairgap=0.254
PlaneConnect [All] p2: planeconnectstyle=Relief reliefexpansion=0.254 reliefentries=4 reliefconductorwidth=0.305 reliefairgap=0.254
PolygonConnect PolygonConnect_via [isvia] p1: connectstyle=Direct reliefconductorwidth=0.254 reliefentries=4 polygonreliefangle="90 Angle"
PolygonConnect [All] p2: connectstyle=Relief reliefconductorwidth=0.254 reliefentries=4 polygonreliefangle="90 Angle"
RoutingVias RoutingVias_mang [OnLayer('Top Layer') and  OnLayer('GND02')  and  OnLayer('ART03')] p1: holewidth=0.203 width=0.406 viastyle="Through Hole" minholewidth=0.203 minwidth=0.406 maxholewidth=0.203 maxwidth=0.406
RoutingVias [All] p2: holewidth=0.203 width=0.406 viastyle="Through Hole" minholewidth=0.203 minwidth=0.406 maxholewidth=0.203 maxwidth=0.406
SilkscreenOverComponentPads [All] p1: minsilkscreentomaskgap=0.254
SolderMaskExpansion SolderMaskExpansion_1 [isvia] p1: expansion=-0.508
SolderMaskExpansion [All] p2: expansion=0.064
Width Width_90 [(InDifferentialPairClass('90'))] p1 off: maxlimit=0.254 minlimit=0.127 preferedwidth=0.254 toplayer_minwidth=0.254 midlayer1_minwidth=0.254 midlayer2_minwidth=0.254 midlayer3_minwidth=0.254 midlayer4_minwidth=0.254 midlayer5_minwidth=0.254 midlayer6_minwidth=0.254 midlayer7_maxwidth=0.127 midlayer7_prefwidth=0.127 midlayer11_minwidth=0.254 bottomlayer_minwidth=0.254 minimp=50.000000 maximp=50.000000 favimp=50.000000
Width Width_DIFF [(InDifferentialPairClass('All Differential Pairs'))] p2: maxlimit=0.107 minlimit=0.089 preferedwidth=0.107 toplayer_maxwidth=0.089 toplayer_prefwidth=0.089 midlayer1_minwidth=0.097 midlayer1_maxwidth=0.097 midlayer1_prefwidth=0.097 midlayer2_minwidth=0.099 midlayer2_maxwidth=0.099 midlayer2_prefwidth=0.099 midlayer3_minwidth=0.099 midlayer3_maxwidth=0.099 midlayer3_prefwidth=0.099 midlayer4_minwidth=0.097 midlayer4_maxwidth=0.097 midlayer4_prefwidth=0.097 midlayer5_maxwidth=0.089 midlayer5_prefwidth=0.089 midlayer6_minwidth=0.107 midlayer7_minwidth=0.107 midlayer11_maxwidth=0.089 midlayer11_prefwidth=0.089 bottomlayer_maxwidth=0.089 bottomlayer_prefwidth=0.089 minimp=50.000000 maximp=50.000000 favimp=50.000000
Width Width_PWR [InNetClass('pwr')] p3: maxlimit=2.54 minlimit=0.152 preferedwidth=0.254
Width [All] p4: maxlimit=2.54 minlimit=0.102 preferedwidth=0.109 toplayer_minwidth=0.114 toplayer_prefwidth=0.114 midlayer1_prefwidth=0.102 midlayer2_minwidth=0.109 midlayer3_minwidth=0.109 midlayer4_prefwidth=0.102 midlayer5_prefwidth=0.102 midlayer6_minwidth=0.119 midlayer6_prefwidth=0.119 midlayer7_minwidth=0.119 midlayer7_prefwidth=0.119 midlayer11_prefwidth=0.102 bottomlayer_minwidth=0.114 bottomlayer_prefwidth=0.114 minimp=50.000000 maximp=50.000000 favimp=50.000000
24 further rules are at their usual default settings.

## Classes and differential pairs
net class usb: USB0-CLK USB0-CLKO USB0-D0 USB0-D1 USB0-D2 USB0-D3 USB0-D4 USB0-D5 USB0-D6 USB0-D7
net class MDIN-DIFF: MDIN0 MDIN1 MDIN2 MDIN3 MDIP0 MDIP1 MDIP2 MDIP3
net class MMC_DATA: MMC-CLK MMC-CMD MMC-D0 MMC-D1 MMC-D2 MMC-D3 MMC-SCLK
component class ZYNQ400-USB: C248 C249 C250 C254 R135 R136 R137 R138 U12 U13
component class ZYNQ400-POWER: C42 C43 C44 C45 C47 C51 C54 C72 C111 C112 C113 C114 C115 C116 C117 C118 C119 C120 C121 C122 C123 C124 C125 C126 F6
component class ZYNQ400-MIO: C30 C31 C32 C33 C34 C35 C36 C37 C38 C39 C40 C41 C46 C48 C147 C148 C213 DONE G1 LD1 R14 R16 R22 R24 R31 R32 R33 R34 R35 R36 R37 R40 R42 R45 R52 R53 R54 R55 R57 R58 R59 R60 R105 U1 U3 U4 U5 U9 X1
component class ZYNQ400-ETH: C24 C25 C26 C27 C28 C29 C141 C142 C143 C144 C145 C146 F2 F7 F8 F9 R1 R2 R3 R4 R13 R15 R17 R18 R19 R20 R21 R106 U2
component class ZYNQ400-EMIO: C8 C9 C12 C13 C14 C15 C16 C17 C18 C19 C20 C21 C22 C23 C241 F1 F3 F4 F5 G2 G3 R27 R28 R29 R133 R144 S0 S1 U17
component class ZYNQ400-DDR: C1 C2 C3 C4 C5 C6 C7 C49 C50 C52 C55 C56 C57 C58 C59 C60 C61 C62 C63 C64 C65 C66 C67 C68 C69 C70 C71 C73 C74 C75 C76 C93 C94 C96 C97 C99 C101 C102 R61 R62 R64 R65 R66 R67 R68 R69 R70 R98 U6 U7 U8
component class ZYNQ400-CONFPC: J1 J2
component class ZYNQ400-CONDIP: J3 R19
component class SYS-PS: C77 C78 C79 C80 C81 C128 C129 C130 C131 C132 C133 C134 C135 C136 C137 C138 C139 C140 R5 R6 R7 R8 R9 R10 R11 R12 R23 R25 R26 R63 U10 U11 U14 U15 U16 U19
net class pwr: AHVDD_CA AVREF AVTT BANK13_VCC BANK34_VCC BANK35_VCC EN_1V0 EN_1V5 EN_1V8 ETHPHY-1V0A ETHPHY_3V3A GND PG_1V0 PG_1V5 PG_3V3 VCC-1V0 VCC-1V8 VCC-IN
net class DDR-ADDR: ADDR3-A0 ADDR3-A1 ADDR3-A2 ADDR3-A3 ADDR3-A4 ADDR3-A5 ADDR3-A6 ADDR3-A7 ADDR3-A8 ADDR3-A9 ADDR3-A10 ADDR3-A11 ADDR3-A12 ADDR3-A13 ADDR3-A14 ADDR3-BA0 ADDR3-BA1 ADDR3-BA2 ADDR3-CAS ADDR3-CKE0 ADDR3-CLK0_N ADDR3-CLK0_P ADDR3-ODT0 ADDR3-RAS ADDR3-RESET ADDR3-S0 ADDR3-WE
net class DDR_D0-D7: ADDR3-D0 ADDR3-D1 ADDR3-D2 ADDR3-D3 ADDR3-D4 ADDR3-D5 ADDR3-D6 ADDR3-D7 ADDR3-DM0 ADDR3-DQS0_N ADDR3-DQS0_P
net class DDR_D8-15: ADDR3-D8 ADDR3-D9 ADDR3-D10 ADDR3-D11 ADDR3-D12 ADDR3-D13 ADDR3-D14 ADDR3-D15 ADDR3-DM1 ADDR3-DQS1_N ADDR3-DQS1_P
net class DDR_D16-23: ADDR3-D16 ADDR3-D17 ADDR3-D18 ADDR3-D19 ADDR3-D20 ADDR3-D21 ADDR3-D22 ADDR3-D23 ADDR3-DM2 ADDR3-DQS2_N ADDR3-DQS2_P
net class DDR_D24-31: ADDR3-D24 ADDR3-D25 ADDR3-D26 ADDR3-D27 ADDR3-D28 ADDR3-D29 ADDR3-D30 ADDR3-D31 ADDR3-DM3 ADDR3-DQS3_N ADDR3-DQS3_P
net class B35-DIFF: B35_L1_N B35_L1_P B35_L2_N B35_L2_P B35_L3_N B35_L3_P B35_L4_N B35_L4_P B35_L5_N B35_L5_P B35_L6_N B35_L6_P B35_L7_N B35_L7_P B35_L8_N B35_L8_P B35_L9_N B35_L9_P B35_L10_N B35_L10_P B35_L11_N B35_L11_P
net class B34-DIFF: B34_L1_N B34_L1_P B34_L2_N B34_L2_P B34_L3_N B34_L3_P B34_L4_N B34_L4_P B34_L5_N B34_L5_P B34_L6_N B34_L6_P B34_L7_N B34_L7_P B34_L8_N B34_L8_P B34_L9_N B34_L9_P B34_L10_N B34_L10_P B34_L11_N B34_L11_P B34_L12_N B34_L12_P B34_L13_N B34_L13_P B34_L14_N B34_L14_P B34_L15_N B34_L15_P B34_L16_N B34_L16_P B34_L17_N B34_L17_P B34_L18_N B34_L18_P B35_L12_N B35_L12_P B35_L13_N B35_L13_P B35_L14_N B35_L14_P B35_L15_N B35_L15_P B35_L16_N B35_L16_P B35_L17_N B35_L17_P
net class B34-DATA: B34_S0 B34_S1 B34_S2 B34_S3 B34_S4 B34_S5 B34_S6 B34_S7 B34_S8 B34_S9 B34_S10 B34_S11
net class B35-DATA: B35_S0 B35_S1 B35_S2 B35_S3 B35_S4 B35_S5
differential pair class 90: USB0
net class B34_C: B34_C0 B34_C1
net class RGMII-TX: RGMII-TXCLK RGMII-TXCTL RGMII-TXD0 RGMII-TXD1 RGMII-TXD2 RGMII-TXD3
net class RGMII-RX: RGMII-RXCLK RGMII-RXCTL RGMII-RXD0 RGMII-RXD1 RGMII-RXD2 RGMII-RXD3
differential pair NewDifferentialPair2: +AVINN -AVINP
differential pair USB0: +USB0-DP -USB0-DM
differential pair ADDR3-DQS3: +ADDR3-DQS3_P -ADDR3-DQS3_N
differential pair ADDR3-DQS2: +ADDR3-DQS2_P -ADDR3-DQS2_N
differential pair ADDR3-DQS1: +ADDR3-DQS1_P -ADDR3-DQS1_N
differential pair ADDR3-DQS0: +ADDR3-DQS0_P -ADDR3-DQS0_N
differential pair ADDR3-CLK0: +ADDR3-CLK0_P -ADDR3-CLK0_N
differential pair D_B35_L17_: +B35_L17_N -B35_L17_P
differential pair D_B35_L16_: +B35_L16_N -B35_L16_P
differential pair D_ADDR3-CLK0_: +ADDR3-CLK0_N -ADDR3-CLK0_P
differential pair D_ADDR3-DQS0_: +ADDR3-DQS0_N -ADDR3-DQS0_P
differential pair D_ADDR3-DQS1_: +ADDR3-DQS1_N -ADDR3-DQS1_P
differential pair D_ADDR3-DQS2_: +ADDR3-DQS2_N -ADDR3-DQS2_P
differential pair D_ADDR3-DQS3_: +ADDR3-DQS3_N -ADDR3-DQS3_P
differential pair D_B34_L1_: +B34_L1_N -B34_L1_P
differential pair D_B34_L2_: +B34_L2_N -B34_L2_P
differential pair D_B34_L3_: +B34_L3_N -B34_L3_P
differential pair D_B34_L4_: +B34_L4_N -B34_L4_P
differential pair D_B34_L5_: +B34_L5_N -B34_L5_P
differential pair D_B34_L6_: +B34_L6_N -B34_L6_P
differential pair D_B34_L7_: +B34_L7_N -B34_L7_P
differential pair D_B34_L8_: +B34_L8_N -B34_L8_P
differential pair D_B34_L9_: +B34_L9_N -B34_L9_P
differential pair D_B34_L10_: +B34_L10_N -B34_L10_P
differential pair D_B34_L11_: +B34_L11_N -B34_L11_P
differential pair D_B34_L12_: +B34_L12_N -B34_L12_P
differential pair D_B34_L13_: +B34_L13_N -B34_L13_P
differential pair D_B34_L14_: +B34_L14_N -B34_L14_P
differential pair D_B34_L15_: +B34_L15_N -B34_L15_P
differential pair D_B34_L16_: +B34_L16_N -B34_L16_P
differential pair D_B34_L17_: +B34_L17_N -B34_L17_P
differential pair D_B34_L18_: +B34_L18_N -B34_L18_P
differential pair D_B35_L1_: +B35_L1_N -B35_L1_P
differential pair D_B35_L2_: +B35_L2_N -B35_L2_P
differential pair D_B35_L3_: +B35_L3_N -B35_L3_P
differential pair D_B35_L4_: +B35_L4_N -B35_L4_P
differential pair D_B35_L5_: +B35_L5_N -B35_L5_P
differential pair D_B35_L6_: +B35_L6_N -B35_L6_P
differential pair D_B35_L7_: +B35_L7_N -B35_L7_P
differential pair D_B35_L8_: +B35_L8_N -B35_L8_P
differential pair D_B35_L9_: +B35_L9_N -B35_L9_P
differential pair D_B35_L10_: +B35_L10_N -B35_L10_P
differential pair D_B35_L11_: +B35_L11_N -B35_L11_P
differential pair D_B35_L12_: +B35_L12_N -B35_L12_P
differential pair D_B35_L13_: +B35_L13_N -B35_L13_P
differential pair D_B35_L14_: +B35_L14_N -B35_L14_P
differential pair D_B35_L15_: +B35_L15_N -B35_L15_P
differential pair D_MDI0: +MDIN0 -MDIP0
differential pair D_MDI1: +MDIN1 -MDIP1
differential pair D_MDI2: +MDIN2 -MDIP2
differential pair D_MDI3: +MDIN3 -MDIP3
differential pair NewDifferentialPair1: +FPGA-STA0 -FPGA-STA1

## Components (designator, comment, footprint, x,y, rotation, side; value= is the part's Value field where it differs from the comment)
C2 "4.7UF/6.3V" 0402 127.381,168.402 r0 bottom
C3 "470nf/6.3V" 0402 127.381,169.545 r0 bottom
C4 "47nf/6.3V" 0402 122.809,169.545 r270 bottom
C5 "470nf/6.3V" 0402 111.592,157.365 r180 bottom
C6 "470nf/6.3V" 0402 109.639,157.365 r180 bottom
C7 "470nf/6.3V" 0402 117.094,159.588 r270 bottom
C8 "470nf/6.3V" 0402 103.353,154.229 r180 top
C9 "470nf/6.3V" 0402 101.27,152.044 r0 top
C12 "470nf/6.3V" 0402 115.533,145.507 r0 bottom
C13 "470nf/6.3V" 0402 111.338,147.765 r180 bottom
C14 "4.7uf/6.3V" 0402 115.062,143.891 r0 bottom
C15 "47uf/6.3V" 0402 117.51,146.753 r0 bottom
C16 "470nf/6.3V" 0402 119.546,147.769 r180 bottom
C17 "470nf/6.3V" 0402 117.5,147.769 r180 bottom
C18 "470nf/6.3V" 0402 110.605,145.102 r180 bottom
C19 "470nf/6.3V" 0402 108.455,144.864 r180 bottom
C20 "4.7uf/6.3V" 0402 110.605,143.765 r180 bottom
C21 "47uf/6.3V" 0402 108.455,143.765 r180 bottom
C22 "470nf/6.3V" 0402 108.404,147.765 r180 bottom
C23 "470nf/6.3V" 0402 108.455,145.943 r180 bottom
C24 "0.1uf/6.3V" 0402 109.728,136.73 r270 bottom
C25 "0.1uf/6.3V" 0402 121.285,139.7 r0 top
C26 "0.1uf/6.3V" 0402 128.473,147.93 r270 bottom
C27 "0.1uf/6.3V" 0402 129.451,139.065 r90 bottom
C28 "0.1uf/6.3V" 0402 123.546,147.93 r270 bottom
C29 "0.1uf/6.3V" 0402 128.27,139.065 r90 bottom
C30 "10UF/6.3V" 0402 101.273,153.086 r0 top
C31 "4.7uf/6.3V" 0402 109.817,152.678 r0 bottom
C32 "470nf/6.3V" 0402 103.353,153.086 r180 top
C33 "47uf/6.3V" 0402 109.817,151.562 r180 bottom
C34 "470nf/6.3V" 0402 108.178,157.884 r270 bottom
C35 "470nf/6.3V" 0402 107.946,151.638 r270 bottom
C36 "470nf/6.3V" 0402 109.817,154.119 r180 bottom
C37 "0.1UF" 0402 103.353,150.835 r180 top
C38 "10uf/6.3V" 0603 102.235,161.925 r180 top
C39 "10UF/6.3V" 0402 115.529,147.769 r180 bottom
C40 "4.7uf/6.3V" 0402 115.529,146.753 r0 bottom
C41 "470nf/6.3V" 0402 111.425,146.325 r180 bottom
C42 "470nf/6.3V" 0402 117.053,148.785 r180 bottom
C43 "470nf/6.3V" 0402 109.817,150.309 r180 bottom
C44 "470nf/6.3V" 0402 113.208,148.785 r0 bottom
C45 "470nf/6.3V" 0402 109.464,149.164 r180 bottom
C46 "0.1UF" 0402 103.353,155.353 r180 top
C47 "470nf/6.3V" 0402 111.338,148.785 r0 bottom
C48 "0.1UF" 0402 110.998,136.73 r90 bottom
C49 "10nF" 0402 115.468,155.883 r270 bottom
C50 "4.7UF/6.3V" 0402 119.507,158.045 r0 bottom
C51 "470nf/6.3V" 0402 109.88,147.345 r270 bottom
C52 "470nf/6.3V" 0402 122.809,167.64 r90 bottom
C53 "100UF/6.3V" 0805 119.475,159.569 r0 bottom
C54 "4.7uf/6.3V" 0402 115.561,154.119 r0 bottom
C55 "4.7UF/6.3V" 0402 105.562,167.436 r270 top
C56 "470nf/6.3V" 0402 122.809,163.83 r90 top
C57 "47nf/6.3V" 0402 122.809,165.735 r270 top
C58 "470nf/6.3V" 0402 122.809,167.64 r90 top
C59 "470nf/6.3V" 0402 122.809,169.545 r270 top
C60 "470nf/6.3V" 0402 122.809,161.925 r270 top
C61 "4.7UF/6.3V" 0402 113.468,157.365 r0 bottom
C62 "470nf/6.3V" 0402 109.639,158.437 r180 bottom
C63 "470nf/6.3V" 0402 121.665,156.565 r270 bottom
C64 "4.7UF/6.3V" 0402 113.03,159.512 r270 bottom
C65 "470nf/6.3V" 0402 124.46,162.941 r0 bottom
C66 "10nF" 0402 111.655,155.765 r0 bottom
C67 "47nf/6.3V" 0402 117.602,158.045 r180 bottom
C68 "4.7UF/6.3V" 0402 109.385,159.834 r0 bottom
C69 "470nf/6.3V" 0402 105.562,169.32 r90 top
C70 "47nf/6.3V" 0402 115.561,157.365 r180 bottom
C71 "470nf/6.3V" 0402 115.561,158.945 r180 bottom
C72 "4.7uf/6.3V" 0402 115.054,148.785 r180 bottom
C73 "470nf/6.3V" 0402 122.809,162.941 r270 bottom
C74 "470nf/6.3V" 0402 114.046,159.512 r270 bottom
C75 "10nF" 0402 105.41,168.326 r180 bottom
C76 "10nF" 0402 114.402,155.876 r270 bottom
C77 "10uf/6.3V" 0603 124.46,159.385 r90 top
C78 "10uf/6.3V" 0603 124.46,156.21 r270 top
C79 "100uf/12V" 0805 128.27,151.13 r270 top
C80 "1uf/12V" 0402 128.27,153.67 r180 top
C81 "1uf/12V" 0402 126.365,153.67 r0 top
C93 "1UF" 0402 127.381,167.259 r0 bottom
C94 "1UF" 0402 129.54,167.259 r180 bottom
C96 "0.1UF" 0402 131.826,168.529 r180 top
C97 "0.1UF" 0402 131.826,167.386 r0 top
C99 "0.1UF" 0402 105.562,163.449 r270 top
C101 "0.1UF" 0402 121.92,159.639 r270 bottom
C102 "0.1UF" 0402 105.41,167.157 r180 bottom
C111 "100uf/6.3V" 0805 111.671,140.265 r270 bottom
C112 "470nf/6.3V" 0402 111.655,154.119 r0 bottom
C113 "470nf/6.3V" 0402 113.627,154.119 r0 bottom
C114 "470nf/6.3V" 0402 115.561,150.309 r0 bottom
C115 "4.7uf/6.3V" 0402 117.561,151.579 r0 bottom
C116 "100uf/6.3V" 0805 122.653,150.72 r270 bottom
C117 "4.7uf/6.3V" 0402 115.561,151.579 r0 bottom
C118 "470nf/6.3V" 0402 115.561,152.692 r180 bottom
C119 "470nf/6.3V" 0402 113.627,152.692 r0 bottom
C120 "470nf/6.3V" 0402 111.719,150.309 r0 bottom
C121 "470nf/6.3V" 0402 111.719,152.692 r0 bottom
C122 "470nf/6.3V" 0402 113.627,151.579 r180 bottom
C123 "470nf/6.3V" 0402 113.627,150.309 r180 bottom
C124 "4.7uf/6.3V" 0402 111.719,151.579 r0 bottom
C125 "10uf/6.3V" 0603 121.196,154.108 r90 bottom
C126 "470nf/6.3V" 0402 121.006,151.511 r270 bottom
C128 "100uf/6.3V" 0805 113.576,140.265 r270 bottom
C129 "100uf/12V" 0805 112.903,136.525 r90 bottom
C130 "10uf/6.3V" 0603 124.46,159.385 r90 bottom
C131 "10uf/6.3V" 0603 124.46,156.21 r270 bottom
C132 "100uf/12V" 0805 128.27,151.13 r270 bottom
C133 "1uf/12V" 0402 128.27,160.02 r180 bottom
C134 "1uf/12V" 0402 128.27,153.67 r0 bottom
C135 "33nf/6.3V" 0402 116.497,136.963 r180 bottom
C136 "10uf/6.3V" 0603 101.6,148.59 r90 top
C137 "10uf/6.3V" 0603 103.505,148.59 r90 top
C138 "100uf/12V" 0805 102.87,141.224 r0 top
C139 "1uf/12V" 0402 100.457,141.224 r270 top
C140 "1uf/12V" 0402 101.346,139.573 r0 top
C144 "0.1uf/6.3V" 0402 121.285,142.24 r0 bottom
C145 "22uf/6.3V" 0603 125.095,147.955 r0 top
C147 "0.1UF" 0402 124.46,161.925 r180 bottom
C148 "47uf/6.3V" 0402 103.353,151.954 r180 top
C213 "0.1uF" 0402 117.561,150.309 r180 bottom
C248 "0.1UF" 0402 125.73,139.065 r90 top
C249 "0.1UF" 0402 122.085,138.106 r270 bottom
C250 "0.1UF" 0402 127,139.065 r90 top
C254 "0.1UF" 0402 121.285,142.24 r180 top
Designator16_7 "Comment" PCBComponent_1#1 96.941,163.969 r270 top
Designator16_8 "Comment" PCBComponent_1#1 96.941,101.969 r270 top
Designator16_9 "Comment" PCBComponent_1#2 96.941,101.969 r270 bottom
Designator16_10 "Comment" PCBComponent_1#2 96.941,163.969 r270 bottom
Designator16_11 "Comment" PCBComponent_1#2 177.941,163.969 r270 bottom
Designator16_12 "Comment" PCBComponent_1#1 177.941,163.969 r270 top
Designator16_13 "Comment" PCBComponent_1#1 177.941,104.969 r270 top
Designator16_14 "Comment" PCBComponent_1#2 177.941,104.969 r270 bottom
DONE "LED" D0402 100.965,165.1 r0 top
F1 "BEAD600R/2A/NC" 0603 119.888,136.398 r0 bottom
F2 "BEAD600R/2A" 0603 124.625,150.62 r270 top
F3 "BEAD600R/2A/NC" 0603 109.22,140.335 r180 bottom
F4 "BEAD600R/2A" 0603 119.888,138.049 r0 bottom
F5 "BEAD600R/2A" 0603 109.22,138.43 r180 bottom
F6 "BEAD600R/2A" 0603 122.72,154.106 r270 bottom
F7 "BEAD600R/2A" 0603 128.27,147.955 r0 top
F8 "BEAD600R/2A" 0603 128.88,137.744 r90 top
F9 "BEAD600R/2A" 0603 126.49,150.62 r270 top
G1 "33.333M/3.3V" 3.2*2.5 102.235,158.445 r180 top
J1 "AXK5S00347YG" AXK5S00347YG 102.982,151.969 r270 bottom locked
J2 "AXK5S00347YG" AXK5S00347YG 133.9,151.969 r90 bottom locked
J3 "AXK6S00647YG" AXK6S00647YG 133.9,151.969 r270 top locked
R1 "4K7" 0402 121.285,140.97 r180 top
R2 "4K7" 0402 121.285,140.97 r180 bottom
R3 "4K7" 0402 127,139.065 r90 bottom
R4 "4K7" 0402 121.451,144.351 r90 bottom
R5 "237K" 0402 124.46,153.67 r0 bottom
R6 "4K7" 0402 116.624,134.931 r180 bottom
R7 "10R" 0402 126.365,160.02 r180 bottom
R8 "158K" 0402 126.365,153.67 r0 bottom
R9 "604K" 0402 116.497,138.106 r180 bottom
R10 "237K" 0402 103.251,138.303 r0 top
R11 "10R" 0402 101.346,138.303 r180 top
R12 "118K" 0402 103.251,139.573 r180 top
R13 "4K7" 0402 124.612,147.93 r270 bottom
R14 "4K7" 0402 131.826,167.386 r0 bottom
R15 "4K7" 0402 125.882,147.93 r90 bottom
R16 "10K" 0402 119.507,152.692 r180 bottom
R17 "4K7" 0402 127.356,147.93 r90 bottom
R18 "4K7" 0402 121.285,139.7 r0 bottom
R19 "4K7" 0402 121.265,147.854 r270 bottom
R20 "4K7" 0402 119.546,146.753 r180 bottom
R21 "2.49K@1%" 0402 129.616,147.93 r90 bottom
R22 "1K@0.1%" 0402 119.507,150.309 r0 bottom
R23 "237K" 0402 126.365,160.02 r0 top
R24 "33R" 0402 119.507,149.166 r0 bottom
R25 "10R" 0402 124.46,153.67 r0 top
R26 "158K" 0402 128.27,160.02 r0 top
R27 "0R/NC" 0402 118.999,141.986 r0 top
R28 "1K" 0402 118.999,140.843 r180 bottom
R29 "1K" 0402 118.999,139.7 r180 bottom
R30 "100R" 0201 102.565,161.468 r270 bottom
R31 "10K" 0402 123.19,137.223 r270 bottom
R32 "10K" 0402 124.46,137.223 r270 bottom
R33 "10K" 0402 125.73,137.223 r270 bottom
R34 "10K" 0402 127.292,136.836 r0 bottom
R35 "1K" 0402 100.965,163.83 r0 top
R36 "10K" 0402 102.87,165.1 r0 top
R37 "10K" 0402 102.87,163.83 r180 top
R38 "100R" 0201 103.378,161.468 r270 bottom
R39 "100R" 0201 133.883,161.569 r90 bottom
R40 "10K" 0402 113.36,155.706 r90 bottom
R41 "100R" 0201 102.565,155.473 r270 bottom
R42 "10K" 0402 119.507,154.119 r180 bottom
R43 "100R" 0201 103.378,155.473 r270 bottom
R44 "100R" 0201 133.248,155.423 r90 bottom
R45 "10K" 0402 117.434,152.692 r180 bottom
R46 "100R" 0201 102.565,153.975 r270 bottom
R47 "100R" 0201 103.378,153.975 r270 bottom
R48 "100R" 0201 133.248,153.899 r90 bottom
R49 "100R" 0201 102.565,152.476 r270 bottom
R50 "100R" 0201 103.378,152.476 r270 bottom
R51 "100R" 0201 133.248,152.375 r90 bottom
R52 "10K" 0402 119.507,155.199 r180 bottom
R53 "10K" 0402 109.131,135.185 r180 bottom
R54 "10K" 0402 108.585,142.24 r90 bottom
R55 "10K" 0402 107.315,142.24 r90 bottom
R56 "100R" 0201 102.565,150.876 r270 bottom
R57 "10K" 0402 109.131,134.169 r180 bottom
R58 "10K" 0402 108.458,136.73 r270 bottom
R59 "33R" 0402 101.296,155.353 r0 top
R60 "10K" 0402 109.855,142.24 r90 bottom
R61 "240R@1%" 0402 115.57,160.02 r180 bottom
R62 "1K@0.1%" 0402 129.54,169.545 r0 bottom
R63 "200K" 0402 116.497,139.249 r0 bottom
R64 "1K@0.1%" 0402 131.826,168.529 r0 bottom
R65 "10K" 0402 131.826,169.672 r180 top
R66 "240R@1%" 0402 105.41,169.545 r180 bottom
R67 "10K" 0402 119.507,156.532 r180 bottom
R68 "10K" 0402 111.973,158.818 r90 bottom
R69 "80.6R@1%" 0402 117.475,155.643 r180 bottom
R70 "80.6R@1%" 0402 117.475,154.178 r180 bottom
R94 "100R" 0201 103.378,150.876 r270 bottom
R95 "100R" 0201 133.248,150.901 r90 bottom
R96 "100R" 0201 102.565,149.403 r270 bottom
R97 "100R" 0201 103.378,149.403 r270 bottom
R98 "DNI/80.6R@1%" 0402 105.562,165.43 r90 top
R103 "100R" 0201 133.248,149.403 r90 bottom
R104 "100R" 0201 102.565,147.955 r270 bottom
R105 "1K@0.1%" 0402 119.507,151.579 r180 bottom
R106 "22R" 0402 122.428,147.854 r270 bottom
R107 "100R" 0201 103.378,147.955 r270 bottom
R108 "100R" 0201 133.248,147.98 r90 bottom
R109 "100R" 0201 102.565,146.456 r270 bottom
R110 "100R" 0201 103.378,146.456 r270 bottom
R111 "100R" 0201 133.248,146.406 r90 bottom
R112 "100R" 0201 102.565,144.958 r270 bottom
R113 "100R" 0201 103.378,144.958 r270 bottom
R114 "100R" 0201 133.248,144.932 r90 bottom
R115 "100R" 0201 102.565,143.459 r270 bottom
R116 "100R" 0201 103.378,143.459 r270 bottom
R117 "100R" 0201 133.248,143.408 r90 bottom
R118 "100R" 0201 102.565,141.961 r270 bottom
R119 "100R" 0201 103.378,141.961 r270 bottom
R120 "100R" 0201 133.248,141.961 r90 bottom
R121 "100R" 0201 102.565,140.462 r270 bottom
R122 "100R" 0201 103.378,140.462 r270 bottom
R123 "100R" 0201 133.248,140.411 r90 bottom
R124 "0R" 0402 107.946,149.643 r90 bottom
R135 "8.06K" 0402 124.46,139.065 r90 top
R136 "1K" 0402 125.73,139.065 r270 bottom
R137 "DNI" 0402 123.19,139.065 r270 top
R138 "10K" 0402 131.826,169.672 r0 bottom
R144 "1K" 0402 118.999,141.986 r180 bottom
RR1 "40.2R@1%" R0402*4 124.46,162.433 r90 top
RR2 "40.2R@1%" R0402*4 124.46,164.719 r270 bottom
RR3 "40.2R@1%" R0402*4 124.46,164.719 r90 top
RR4 "40.2R@1%" R0402*4 124.46,169.291 r90 top
RR5 "40.2R@1%" R0402*4 124.46,167.005 r270 bottom
RR6 "40.2R@1%" R0402*4 124.46,169.291 r270 bottom
RR7 "40.2R@1%" R0402*4 124.46,167.005 r90 top
S0 "LED" D0402 118.999,140.843 r180 top
S1 "LED" D0402 118.999,139.7 r180 top
U1 "XC7Z020CLG400" CLG400 113.665,151.765 r270 top locked
U2 "RTL8211FDI" QFN40 127,143.51 r180 bottom
U3 "MAX6822SUK-T" MAX6822SUK 128.27,163.83 r0 top
U4 "TLV70518YFPT" WCSP-4 107.95,153.975 r0 bottom
U5 "S25FL256SAGNFI00" MLP8 107.95,138.43 r180 top
U6 "MT41J128M16HA-187E:D" FBGA96 114.3,165.735 r270 bottom locked
U7 "MAX1510ETB" TQFN 128.524,168.275 r90 top
U8 "MT41J128M16HA-187E:D" FBGA96 114.3,165.735 r90 top locked
U9 "REF3312AIDCKT" SOT323 108.952,155.763 r90 bottom
U10 "EN6347QI" EN6347-QFN 114.935,138.43 r270 top
U11 "EP53F8QI" QFN16 127.635,156.845 r90 bottom
U12 "USB3320" QFN32 127,143.51 r180 top
U13 "TPS2051BDBV" SOT23-5 128.27,163.83 r180 bottom
U14 "EP53F8QI" QFN16 102.235,144.78 r180 top
U15 "SN74LVC1G97DCK" SC70-DCK 106.045,135.255 r0 bottom
U16 "SN74LVC1G97DCK" SC70-DCK 125.73,151.13 r0 bottom
U17 "74AVC1T45" SOT363 118.745,144.145 r90 bottom
U18 "DS28E01-100" TSOC 120.015,135.89 r180 top
U19 "EP538QFI" QFN16 127.635,156.845 r270 top
X1 "JTAG" 1.27*6 123.19,134.62 r0 top

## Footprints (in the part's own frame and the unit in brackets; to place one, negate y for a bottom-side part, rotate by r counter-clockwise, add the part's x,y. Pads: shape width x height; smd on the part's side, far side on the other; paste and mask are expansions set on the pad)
1.27*6 [mm]
  rect 1.05x1.05 hole 0.6: 1(0,0)
  round 1.05 hole 0.6: 2(1.27,0) 3(2.54,0) 4(3.81,0) 5(5.08,0) 6(6.35,0)
  silkscreen extent -0.82,-1.07 7.17,1.07
3.2*2.5 [mm]
  rect 1.4x1.2 smd: 1(-1.2,-0.95) 2(1.2,-0.95) 3(1.2,0.95) 4(-1.2,0.95)
  silkscreen extent -1.79,-2.36 1.6,1.25
0201 [mm]
  rect 0.4x0.4 smd: 1(-0.32,0) 2(0.32,0)
  silkscreen extent -0.7,-0.4 0.7,0.4
0402 [mm]
  rect 0.51x0.51 smd: 1(-0.41,0) 2(0.41,0)
  silkscreen extent -0.91,-0.5 0.91,0.5
0603 [mm]
  rect 0.76x0.8 smd: 1(-0.76,0) 2(0.76,0)
  silkscreen extent -1.46,-0.7 1.46,0.7
0805 [mm]
  rect 1.016x1.27 smd: 1(-1,0) 2(1,0)
  silkscreen extent -1.8,-0.9 1.8,0.9
AXK5S00347YG [mm]
  rect 0.275x2 smd: 1(-12.25,2.2) 2(-11.75,2.2) 3(-11.25,2.2) 4(-10.75,2.2) 5(-10.25,2.2) 6(-9.75,2.2) 7(-9.25,2.2) 8(-8.75,2.2) 9(-8.25,2.2) 10(-7.75,2.2) 11(-7.25,2.2) 12(-6.75,2.2) 13(-6.25,2.2) 14(-5.75,2.2) 15(-5.25,2.2) 16(-4.75,2.2) 17(-4.25,2.2) 18(-3.75,2.2) 19(-3.25,2.2) 20(-2.75,2.2) 21(-2.25,2.2) 22(-1.75,2.2) 23(-1.25,2.2) 24(-0.75,2.2) 25(-0.25,2.2) 26(0.25,2.2) 27(0.75,2.2) 28(1.25,2.2) 29(1.75,2.2) 30(2.25,2.2) 31(2.75,2.2) 32(3.25,2.2) 33(3.75,2.2) 34(4.25,2.2) 35(4.75,2.2) 36(5.25,2.2) 37(5.75,2.2) 38(6.25,2.2) 39(6.75,2.2) 40(7.25,2.2) 41(7.75,2.2) 42(8.25,2.2) 43(8.75,2.2) 44(9.25,2.2) 45(9.75,2.2) 46(10.25,2.2) 47(10.75,2.2) 48(11.25,2.2) 49(11.75,2.2) 50(12.25,2.2) 51(-12.25,-2.2) 52(-11.75,-2.2) 53(-11.25,-2.2) 54(-10.75,-2.2) 55(-10.25,-2.2) 56(-9.75,-2.2) 57(-9.25,-2.2) 58(-8.75,-2.2) 59(-8.25,-2.2) 60(-7.75,-2.2) 61(-7.25,-2.2) 62(-6.75,-2.2) 63(-6.25,-2.2) 64(-5.75,-2.2) 65(-5.25,-2.2) 66(-4.75,-2.2) 67(-4.25,-2.2) 68(-3.75,-2.2) 69(-3.25,-2.2) 70(-2.75,-2.2) 71(-2.25,-2.2) 72(-1.75,-2.2) 73(-1.25,-2.2) 74(-0.75,-2.2) 75(-0.25,-2.2) 76(0.25,-2.2) 77(0.75,-2.2) 78(1.25,-2.2) 79(1.75,-2.2) 80(2.25,-2.2) 81(2.75,-2.2) 82(3.25,-2.2) 83(3.75,-2.2) 84(4.25,-2.2) 85(4.75,-2.2) 86(5.25,-2.2) 87(5.75,-2.2) 88(6.25,-2.2) 89(6.75,-2.2) 90(7.25,-2.2) 91(7.75,-2.2) 92(8.25,-2.2) 93(8.75,-2.2) 94(9.25,-2.2) 95(9.75,-2.2) 96(10.25,-2.2) 97(10.75,-2.2) 98(11.25,-2.2) 99(11.75,-2.2) 100(12.25,-2.2)
  rect 0.4x1.6 smd: ""(-13.25,0) ""(13.25,0)
  silkscreen extent -14.1,-2.3 14.1,2.3
AXK6S00647YG [mm]
  rect 0.275x2 smd: 1(12.25,2) 2(11.75,2) 3(11.25,2) 4(10.75,2) 5(10.25,2) 6(9.75,2) 7(9.25,2) 8(8.75,2) 9(8.25,2) 10(7.75,2) 11(7.25,2) 12(6.75,2) 13(6.25,2) 14(5.75,2) 15(5.25,2) 16(4.75,2) 17(4.25,2) 18(3.75,2) 19(3.25,2) 20(2.75,2) 21(2.25,2) 22(1.75,2) 23(1.25,2) 24(0.75,2) 25(0.25,2) 26(-0.25,2) 27(-0.75,2) 28(-1.25,2) 29(-1.75,2) 30(-2.25,2) 31(-2.75,2) 32(-3.25,2) 33(-3.75,2) 34(-4.25,2) 35(-4.75,2) 36(-5.25,2) 37(-5.75,2) 38(-6.25,2) 39(-6.75,2) 40(-7.25,2) 41(-7.75,2) 42(-8.25,2) 43(-8.75,2) 44(-9.25,2) 45(-9.75,2) 46(-10.25,2) 47(-10.75,2) 48(-11.25,2) 49(-11.75,2) 50(-12.25,2) 51(12.25,-2) 52(11.75,-2) 53(11.25,-2) 54(10.75,-2) 55(10.25,-2) 56(9.75,-2) 57(9.25,-2) 58(8.75,-2) 59(8.25,-2) 60(7.75,-2) 61(7.25,-2) 62(6.75,-2) 63(6.25,-2) 64(5.75,-2) 65(5.25,-2) 66(4.75,-2) 67(4.25,-2) 68(3.75,-2) 69(3.25,-2) 70(2.75,-2) 71(2.25,-2) 72(1.75,-2) 73(1.25,-2) 74(0.75,-2) 75(0.25,-2) 76(-0.25,-2) 77(-0.75,-2) 78(-1.25,-2) 79(-1.75,-2) 80(-2.25,-2) 81(-2.75,-2) 82(-3.25,-2) 83(-3.75,-2) 84(-4.25,-2) 85(-4.75,-2) 86(-5.25,-2) 87(-5.75,-2) 88(-6.25,-2) 89(-6.75,-2) 90(-7.25,-2) 91(-7.75,-2) 92(-8.25,-2) 93(-8.75,-2) 94(-9.25,-2) 95(-9.75,-2) 96(-10.25,-2) 97(-10.75,-2) 98(-11.25,-2) 99(-11.75,-2) 100(-12.25,-2)
  rect 0.4x1.6 smd: ""(-13.25,-0.2) ""(13.25,-0.2)
  silkscreen extent -14.1,-2.1 14.1,2.1
CLG400 [mm]
  round 0.4 smd: A1(-7.6,7.6) A2(-6.8,7.6) A3(-6,7.6) A4(-5.2,7.6) A5(-4.4,7.6) A6(-3.6,7.6) A7(-2.8,7.6) A8(-2,7.6) A9(-1.2,7.6) A10(-0.4,7.6) A11(0.4,7.6) A12(1.2,7.6) A13(2,7.6) A14(2.8,7.6) A15(3.6,7.6) A16(4.4,7.6) A17(5.2,7.6) A18(6,7.6) A19(6.8,7.6) A20(7.6,7.6) B1(-7.6,6.8) B2(-6.8,6.8) B3(-6,6.8) B4(-5.2,6.8) B5(-4.4,6.8) B6(-3.6,6.8) B7(-2.8,6.8) B8(-2,6.8) B9(-1.2,6.8) B10(-0.4,6.8) B11(0.4,6.8) B12(1.2,6.8) B13(2,6.8) B14(2.8,6.8) B15(3.6,6.8) B16(4.4,6.8) B17(5.2,6.8) B18(6,6.8) B19(6.8,6.8) B20(7.6,6.8) C1(-7.6,6) C2(-6.8,6) C3(-6,6) C4(-5.2,6) C5(-4.4,6) C6(-3.6,6) C7(-2.8,6) C8(-2,6) C9(-1.2,6) C10(-0.4,6) C11(0.4,6) C12(1.2,6) C13(2,6) C14(2.8,6) C15(3.6,6) C16(4.4,6) C17(5.2,6) C18(6,6) C19(6.8,6) C20(7.6,6) D1(-7.6,5.2) D2(-6.8,5.2) D3(-6,5.2) D4(-5.2,5.2) D5(-4.4,5.2) D6(-3.6,5.2) D7(-2.8,5.2) D8(-2,5.2) D9(-1.2,5.2) D10(-0.4,5.2) D11(0.4,5.2) D12(1.2,5.2) D13(2,5.2) D14(2.8,5.2) D15(3.6,5.2) D16(4.4,5.2) D17(5.2,5.2) D18(6,5.2) D19(6.8,5.2) D20(7.6,5.2) E1(-7.6,4.4) E2(-6.8,4.4) E3(-6,4.4) E4(-5.2,4.4) E5(-4.4,4.4) E6(-3.6,4.4) E7(-2.8,4.4) E8(-2,4.4) E9(-1.2,4.4) E10(-0.4,4.4) E11(0.4,4.4) E12(1.2,4.4) E13(2,4.4) E14(2.8,4.4) E15(3.6,4.4) E16(4.4,4.4) E17(5.2,4.4) E18(6,4.4) E19(6.8,4.4) E20(7.6,4.4) F1(-7.6,3.6) F2(-6.8,3.6) F3(-6,3.6) F4(-5.2,3.6) F5(-4.4,3.6) F6(-3.6,3.6) F7(-2.8,3.6) F8(-2,3.6) F9(-1.2,3.6) F10(-0.4,3.6) F11(0.4,3.6) F12(1.2,3.6) F13(2,3.6) F14(2.8,3.6) F15(3.6,3.6) F16(4.4,3.6) F17(5.2,3.6) F18(6,3.6) F19(6.8,3.6) F20(7.6,3.6) G1(-7.6,2.8) G2(-6.8,2.8) G3(-6,2.8) G4(-5.2,2.8) G5(-4.4,2.8) G6(-3.6,2.8) G7(-2.8,2.8) G8(-2,2.8) G9(-1.2,2.8) G10(-0.4,2.8) G11(0.4,2.8) G12(1.2,2.8) G13(2,2.8) G14(2.8,2.8) G15(3.6,2.8) G16(4.4,2.8) G17(5.2,2.8) G18(6,2.8) G19(6.8,2.8) G20(7.6,2.8) H1(-7.6,2) H2(-6.8,2) H3(-6,2) H4(-5.2,2) H5(-4.4,2) H6(-3.6,2) H7(-2.8,2) H8(-2,2) H9(-1.2,2) H10(-0.4,2) H11(0.4,2) H12(1.2,2) H13(2,2) H14(2.8,2) H15(3.6,2) H16(4.4,2) H17(5.2,2) H18(6,2) H19(6.8,2) H20(7.6,2) J1(-7.6,1.2) J2(-6.8,1.2) J3(-6,1.2) J4(-5.2,1.2) J5(-4.4,1.2) J6(-3.6,1.2) J7(-2.8,1.2) J8(-2,1.2) J9(-1.2,1.2) J10(-0.4,1.2) J11(0.4,1.2) J12(1.2,1.2) J13(2,1.2) J14(2.8,1.2) J15(3.6,1.2) J16(4.4,1.2) J17(5.2,1.2) J18(6,1.2) J19(6.8,1.2) J20(7.6,1.2) K1(-7.6,0.4) K2(-6.8,0.4) K3(-6,0.4) K4(-5.2,0.4) K5(-4.4,0.4) K6(-3.6,0.4) K7(-2.8,0.4) K8(-2,0.4) K9(-1.2,0.4) K10(-0.4,0.4) K11(0.4,0.4) K12(1.2,0.4) K13(2,0.4) K14(2.8,0.4) K15(3.6,0.4) K16(4.4,0.4) K17(5.2,0.4) K18(6,0.4) K19(6.8,0.4) K20(7.6,0.4) L1(-7.6,-0.4) L2(-6.8,-0.4) L3(-6,-0.4) L4(-5.2,-0.4) L5(-4.4,-0.4) L6(-3.6,-0.4) L7(-2.8,-0.4) L8(-2,-0.4) L9(-1.2,-0.4) L10(-0.4,-0.4) L11(0.4,-0.4) L12(1.2,-0.4) L13(2,-0.4) L14(2.8,-0.4) L15(3.6,-0.4) L16(4.4,-0.4) L17(5.2,-0.4) L18(6,-0.4) L19(6.8,-0.4) L20(7.6,-0.4) M1(-7.6,-1.2) M2(-6.8,-1.2) M3(-6,-1.2) M4(-5.2,-1.2) M5(-4.4,-1.2) M6(-3.6,-1.2) M7(-2.8,-1.2) M8(-2,-1.2) M9(-1.2,-1.2) M10(-0.4,-1.2) M11(0.4,-1.2) M12(1.2,-1.2) M13(2,-1.2) M14(2.8,-1.2) M15(3.6,-1.2) M16(4.4,-1.2) M17(5.2,-1.2) M18(6,-1.2) M19(6.8,-1.2) M20(7.6,-1.2) N1(-7.6,-2) N2(-6.8,-2) N3(-6,-2) N4(-5.2,-2) N5(-4.4,-2) N6(-3.6,-2) N7(-2.8,-2) N8(-2,-2) N9(-1.2,-2) N10(-0.4,-2) N11(0.4,-2) N12(1.2,-2) N13(2,-2) N14(2.8,-2) N15(3.6,-2) N16(4.4,-2) N17(5.2,-2) N18(6,-2) N19(6.8,-2) N20(7.6,-2) P1(-7.6,-2.8) P2(-6.8,-2.8) P3(-6,-2.8) P4(-5.2,-2.8) P5(-4.4,-2.8) P6(-3.6,-2.8) P7(-2.8,-2.8) P8(-2,-2.8) P9(-1.2,-2.8) P10(-0.4,-2.8) P11(0.4,-2.8) P12(1.2,-2.8) P13(2,-2.8) P14(2.8,-2.8) P15(3.6,-2.8) P16(4.4,-2.8) P17(5.2,-2.8) P18(6,-2.8) P19(6.8,-2.8) P20(7.6,-2.8) R1(-7.6,-3.6) R2(-6.8,-3.6) R3(-6,-3.6) R4(-5.2,-3.6) R5(-4.4,-3.6) R6(-3.6,-3.6) R7(-2.8,-3.6) R8(-2,-3.6) R9(-1.2,-3.6) R10(-0.4,-3.6) R11(0.4,-3.6) R12(1.2,-3.6) R13(2,-3.6) R14(2.8,-3.6) R15(3.6,-3.6) R16(4.4,-3.6) R17(5.2,-3.6) R18(6,-3.6) R19(6.8,-3.6) R20(7.6,-3.6) T1(-7.6,-4.4) T2(-6.8,-4.4) T3(-6,-4.4) T4(-5.2,-4.4) T5(-4.4,-4.4) T6(-3.6,-4.4) T7(-2.8,-4.4) T8(-2,-4.4) T9(-1.2,-4.4) T10(-0.4,-4.4) T11(0.4,-4.4) T12(1.2,-4.4) T13(2,-4.4) T14(2.8,-4.4) T15(3.6,-4.4) T16(4.4,-4.4) T17(5.2,-4.4) T18(6,-4.4) T19(6.8,-4.4) T20(7.6,-4.4) U1(-7.6,-5.2) U2(-6.8,-5.2) U3(-6,-5.2) U4(-5.2,-5.2) U5(-4.4,-5.2) U6(-3.6,-5.2) U7(-2.8,-5.2) U8(-2,-5.2) U9(-1.2,-5.2) U10(-0.4,-5.2) U11(0.4,-5.2) U12(1.2,-5.2) U13(2,-5.2) U14(2.8,-5.2) U15(3.6,-5.2) U16(4.4,-5.2) U17(5.2,-5.2) U18(6,-5.2) U19(6.8,-5.2) U20(7.6,-5.2) V1(-7.6,-6) V2(-6.8,-6) V3(-6,-6) V4(-5.2,-6) V5(-4.4,-6) V6(-3.6,-6) V7(-2.8,-6) V8(-2,-6) V9(-1.2,-6) V10(-0.4,-6) V11(0.4,-6) V12(1.2,-6) V13(2,-6) V14(2.8,-6) V15(3.6,-6) V16(4.4,-6) V17(5.2,-6) V18(6,-6) V19(6.8,-6) V20(7.6,-6) W1(-7.6,-6.8) W2(-6.8,-6.8) W3(-6,-6.8) W4(-5.2,-6.8) W5(-4.4,-6.8) W6(-3.6,-6.8) W7(-2.8,-6.8) W8(-2,-6.8) W9(-1.2,-6.8) W10(-0.4,-6.8) W11(0.4,-6.8) W12(1.2,-6.8) W13(2,-6.8) W14(2.8,-6.8) W15(3.6,-6.8) W16(4.4,-6.8) W17(5.2,-6.8) W18(6,-6.8) W19(6.8,-6.8) W20(7.6,-6.8) Y1(-7.6,-7.6) Y2(-6.8,-7.6) Y3(-6,-7.6) Y4(-5.2,-7.6) Y5(-4.4,-7.6) Y6(-3.6,-7.6) Y7(-2.8,-7.6) Y8(-2,-7.6) Y9(-1.2,-7.6) Y10(-0.4,-7.6) Y11(0.4,-7.6) Y12(1.2,-7.6) Y13(2,-7.6) Y14(2.8,-7.6) Y15(3.6,-7.6) Y16(4.4,-7.6) Y17(5.2,-7.6) Y18(6,-7.6) Y19(6.8,-7.6) Y20(7.6,-7.6)
  silkscreen extent -8.5,-8.5 8.5,8.5
D0402 [mm]
  rect 0.51x0.51 smd: 1(-0.41,0) 2(0.41,0)
  silkscreen extent -0.91,-0.5 0.91,0.5
EN6347-QFN [mm]
  oval 0.8x0.28 smd: 1(-3.5,1.25) 2(-3.5,0.75) 3(-3.5,0.25) 4(-3.5,-0.25) 5(-3.5,-0.75) 6(-3.5,-1.25) 20(3.5,-1.25) 21(3.5,-0.75) 22(3.5,-0.25) 23(3.5,0.25) 24(3.5,0.75) 25(3.5,1.25)
  oval 0.28x0.8 smd: 7(-3,-2) 8(-2.5,-2) 9(-2,-2) 10(-1.5,-2) 11(-1,-2) 12(-0.5,-2) 13(0,-2) 14(0.5,-2) 15(1,-2) 16(1.5,-2) 17(2,-2) 18(2.5,-2) 19(3,-2) 26(3,2) 27(2.5,2) 28(2,2) 29(1.5,2) 30(1,2) 31(0.5,2) 32(0,2) 33(-0.5,2) 34(-1,2) 35(-1.5,2) 36(-2,2) 37(-2.5,2) 38(-3,2)
  rect 1.94x2.6 smd: 39(1.255,0)
  silkscreen extent -4.47,-2 3.5,2.11
FBGA96 [mm]
  round 0.4 smd: A1(-3.2,6) A2(-2.4,6) A3(-1.6,6) A7(1.6,6) A8(2.4,6) A9(3.2,6) B1(-3.2,5.2) B2(-2.4,5.2) B3(-1.6,5.2) B7(1.6,5.2) B8(2.4,5.2) B9(3.2,5.2) C1(-3.2,4.4) C2(-2.4,4.4) C3(-1.6,4.4) C7(1.6,4.4) C8(2.4,4.4) C9(3.2,4.4) D1(-3.2,3.6) D2(-2.4,3.6) D3(-1.6,3.6) D7(1.6,3.6) D8(2.4,3.6) D9(3.2,3.6) E1(-3.2,2.8) E2(-2.4,2.8) E3(-1.6,2.8) E7(1.6,2.8) E8(2.4,2.8) E9(3.2,2.8) F1(-3.2,2) F2(-2.4,2) F3(-1.6,2) F7(1.6,2) F8(2.4,2) F9(3.2,2) G1(-3.2,1.2) G2(-2.4,1.2) G3(-1.6,1.2) G7(1.6,1.2) G8(2.4,1.2) G9(3.2,1.2) H1(-3.2,0.4) H2(-2.4,0.4) H3(-1.6,0.4) H7(1.6,0.4) H8(2.4,0.4) H9(3.2,0.4) J1(-3.2,-0.4) J2(-2.4,-0.4) J3(-1.6,-0.4) J7(1.6,-0.4) J8(2.4,-0.4) J9(3.2,-0.4) K1(-3.2,-1.2) K2(-2.4,-1.2) K3(-1.6,-1.2) K7(1.6,-1.2) K8(2.4,-1.2) K9(3.2,-1.2) L1(-3.2,-2) L2(-2.4,-2) L3(-1.6,-2) L7(1.6,-2) L8(2.4,-2) L9(3.2,-2) M1(-3.2,-2.8) M2(-2.4,-2.8) M3(-1.6,-2.8) M7(1.6,-2.8) M8(2.4,-2.8) M9(3.2,-2.8) N1(-3.2,-3.6) N2(-2.4,-3.6) N3(-1.6,-3.6) N7(1.6,-3.6) N8(2.4,-3.6) N9(3.2,-3.6) P1(-3.2,-4.4) P2(-2.4,-4.4) P3(-1.6,-4.4) P7(1.6,-4.4) P8(2.4,-4.4) P9(3.2,-4.4) R1(-3.2,-5.2) R2(-2.4,-5.2) R3(-1.6,-5.2) R7(1.6,-5.2) R8(2.4,-5.2) R9(3.2,-5.2) T1(-3.2,-6) T2(-2.4,-6) T3(-1.6,-6) T7(1.6,-6) T8(2.4,-6) T9(3.2,-6)
  silkscreen extent -4.5,-7 4.5,7
MAX6822SUK [mm]
  rect 0.6x1.4 smd: 1(-0.95,-1.3) 2(0,-1.3) 3(0.95,-1.3) 4(0.95,1.3) 5(-0.95,1.3)
  silkscreen extent -2.08,-2.38 1.5,0.3
MLP8 [mm]
  oval 0.6x1.1 smd: 1(-1.905,-3.95) 2(-0.635,-3.95) 3(0.635,-3.95) 4(1.905,-3.95) 5(1.905,3.95) 6(0.635,3.95) 7(-0.635,3.95) 8(-1.905,3.95)
  rect 4.8x4.65 smd: 9(0,0)
  silkscreen extent -3.71,-4.57 3,4
PCBComponent_1#1 [mm]
  round 2 on Top Solder: 0(0,0)
  round 1 smd: 1(0,0)
  Top Layer lines w0.254: 0.6,-1.4 1.4,-0.6 1.4,0.6 0.6,1.4 0.4,1.4 -0.4,1.4 -0.6,1.4 -1.4,0.6 -1.4,-0.6 -0.6,-1.4 0.6,-1.4
PCBComponent_1#2 [mm]
  round 2 on Bottom Solder: 0(0,0)
  round 1 smd: 1(0,0)
  Top Layer lines w0.254: 0.6,1.4 0.4,1.4 -0.4,1.4 -0.6,1.4 -1.4,0.6 -1.4,-0.6 -0.6,-1.4 0.6,-1.4 1.4,-0.6 1.4,0.6 0.6,1.4
QFN16 [mm]
  oval 0.8x0.28 smd: 1(-1.5,1.25) 2(-1.5,0.75) 3(-1.5,0.25) 4(-1.5,-0.25) 5(-1.5,-0.75) 6(-1.5,-1.25) 9(1.5,-1.25) 10(1.5,-0.75) 11(1.5,-0.25) 12(1.5,0.25) 13(1.5,0.75) 14(1.5,1.25)
  oval 0.28x0.8 smd: 7(-0.25,-1.5) 8(0.25,-1.5) 15(0.25,1.5) 16(-0.25,1.5)
  silkscreen extent -2.64,-1.65 1.5,2.31
QFN32 [mm]
  oval 0.8x0.28 smd: 1(-2.4,1.75) 2(-2.4,1.25) 3(-2.4,0.75) 4(-2.4,0.25) 5(-2.4,-0.25) 6(-2.4,-0.75) 7(-2.4,-1.25) 8(-2.4,-1.75) 17(2.4,-1.75) 18(2.4,-1.25) 19(2.4,-0.75) 20(2.4,-0.25) 21(2.4,0.25) 22(2.4,0.75) 23(2.4,1.25) 24(2.4,1.75)
  oval 0.28x0.8 smd: 9(-1.75,-2.4) 10(-1.25,-2.4) 11(-0.75,-2.4) 12(-0.25,-2.4) 13(0.25,-2.4) 14(0.75,-2.4) 15(1.25,-2.4) 16(1.75,-2.4) 25(1.75,2.4) 26(1.25,2.4) 27(0.75,2.4) 28(0.25,2.4) 29(-0.25,2.4) 30(-0.75,2.4) 31(-1.25,2.4) 32(-1.75,2.4)
  rect 3.3x3.3 smd: 33(0,0)
  silkscreen extent -3.6,-2.5 2.5,2.5
QFN40 [mm]
  oval 0.8x0.2 smd: 1(-2.5,1.8) 2(-2.5,1.4) 3(-2.5,1) 4(-2.5,0.6) 5(-2.5,0.2) 6(-2.5,-0.2) 7(-2.5,-0.6) 8(-2.5,-1) 9(-2.5,-1.4) 10(-2.5,-1.8) 21(2.5,-1.8) 22(2.5,-1.4) 23(2.5,-1) 24(2.5,-0.6) 25(2.5,-0.2) 26(2.5,0.2) 27(2.5,0.6) 28(2.5,1) 29(2.5,1.4) 30(2.5,1.8)
  oval 0.2x0.8 smd: 11(-1.8,-2.5) 12(-1.4,-2.5) 13(-1,-2.5) 14(-0.6,-2.5) 15(-0.2,-2.5) 16(0.2,-2.5) 17(0.6,-2.5) 18(1,-2.5) 19(1.4,-2.5) 20(1.8,-2.5) 31(1.8,2.5) 32(1.4,2.5) 33(1,2.5) 34(0.6,2.5) 35(0.2,2.5) 36(-0.2,2.5) 37(-0.6,2.5) 38(-1,2.5) 39(-1.4,2.5) 40(-1.8,2.5)
  rect 3.7x3.7 smd: 41(0,0)
  silkscreen extent -2.5,-2.5 2.5,2.5
R0402*4 [mm]
  rect 0.3x0.6 smd: 1(-0.77,-0.5) 4(0.77,-0.5) 5(0.77,0.5) 8(-0.77,0.5)
  rect 0.25x0.6 smd: 2(-0.25,-0.5) 3(0.25,-0.5) 6(0.25,0.5) 7(-0.25,0.5)
  silkscreen extent -1.15,-0.5 1.15,0.6
SC70-DCK [mm]
  rect 0.4x1.2 smd: 1(-0.65,-1) 2(0,-1) 3(0.65,-1) 4(0.65,1) 5(0,1) 6(-0.65,1)
  silkscreen extent -1.1,-2.42 1.1,0.18
SOT23-5 [mm]
  rect 0.6x1.4 smd: 1(-0.95,-1.3) 2(0,-1.3) 3(0.95,-1.3) 4(0.95,1.3) 5(-0.95,1.3)
  silkscreen extent -2.08,-2.38 1.5,0.3
SOT323 [mm]
  rect 0.5x0.9 smd: 1(-0.65,-0.9) 2(0.65,-0.9) 3(0,0.9)
  silkscreen extent -1,-0.7 1,0.7
SOT363 [mm]
  rect 0.35x1.2 smd: 1(-0.65,-1) 2(0,-1) 3(0.65,-1) 4(0.65,1) 5(0,1) 6(-0.65,1)
  silkscreen extent -1.1,-1.85 1.1,1.85
TQFN [mm]
  oval 0.28x0.8 smd: 1(-1,-1.5) 2(-0.5,-1.5) 3(0,-1.5) 4(0.5,-1.5) 5(1,-1.5) 6(1,1.5) 7(0.5,1.5) 8(0,1.5) 9(-0.5,1.5) 10(-1,1.5)
  rect 2.3x1.5 smd: P(0,0)
  silkscreen extent -2.08,-2.26 1.5,1.5
TSOC [mm]
  oval 0.6x1.4 smd: 1(-1.27,-1.959) 2(0,-1.959) 3(1.27,-1.959) 4(1.27,1.959) 5(0,1.959) 6(-1.27,1.959)
  silkscreen extent -2.29,-3.02 2,1
WCSP-4 [mm]
  round 0.2 smd: A1(-0.2,0.2) A2(0.2,0.2) B1(-0.2,-0.2) B2(0.2,-0.2)
  silkscreen extent -0.6,-0.6 0.6,0.6

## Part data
C2 C3 C4 C5 C6 C7 C8 C9 C12 C13 C14 C15 C16 C17 C18 C19 C20 C21 C22 C23 C24 C25 C26 C27 C28 C29 C30 C31 C32 C33 C34 C35 C36 C37 C38 C39 C40 C41 C42 C43 C44 C45 C46 C47 C48 C49 C50 C51 C52 C53 C54 C55 C56 C57 C58 C59 C60 C61 C62 C63 C64 C65 C66 C67 C68 C69 C70 C71 C72 C73 C74 C75 C76 C77 C78 C79 C80 C81 C93 C94 C96 C97 C99 C101 C102 C111 C112 C113 C114 C115 C116 C117 C118 C119 C120 C121 C122 C123 C124 C125 C126 C128 C129 C130 C131 C132 C133 C134 C135 C136 C137 C138 C139 C140 C144 C145 C147 C148 C213: library part CAPACITOR, "Generic Capacitor"
C248 C249 C250 C254: library part Cap, "Capacitor"
DONE S0 S1: library part LED0, "Typical INFRARED GaAs LED"
F1 F2 F3 F4 F5 F6 F7 F8 F9: library part Inductor, "Inductor"
G1: library part FXO-HC5, "3.3V HCMOS Oscillator"
J2: library part AXK6S00647YG
R1 R2 R3 R4 R13 R15 R17 R18 R19 R20 R21 R135 R136 R137 R138 R144: library part Res1, "Resistor"
R5 R6 R7 R8 R9 R10 R11 R12 R14 R16 R22 R23 R24 R25 R26 R27 R28 R29 R30 R31 R32 R33 R34 R35 R36 R37 R38 R39 R40 R41 R42 R43 R44 R45 R46 R47 R48 R49 R50 R51 R52 R53 R54 R55 R56 R57 R58 R59 R60 R61 R62 R63 R64 R65 R66 R67 R68 R69 R70 R94 R95 R96 R97 R98 R103 R104 R105 R106 R107 R108 R109 R110 R111 R112 R113 R114 R115 R116 R117 R118 R119 R120 R121 R122 R123 R124: library part RESISTOR, "Generic Resistor"
RR1 RR2 RR3 RR4 RR5 RR6 RR7: library part "Res -4", "Isolated Resistor Network"
U1: library part XC7Z020-CLG400, "Zynq 7000 FPGA 20 Die, in a CSG 484 Package"
U5: library part N25Q12-F8, "Serial Flash Memory, 16Mbit, Low Voltage, 50MHz SPI Bus Interface"
U6 U8: library part MT41JxxxMxx, "DDR3 SDRAM 2Gb x4, x8, x16"
U7: library part MAX1510, "Low-Voltage, DDR Linear Regulators"
U12: library part USB3320C-EZK
U13: library part TPS2051
U18: library part "Header 3X2A", "Header, 3-Pin, Dual row"
X1: library part "Header 6", "Header, 6-Pin"

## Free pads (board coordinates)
  round 3 hole 3 unplated: 0(96.941,97.969) 0(96.941,167.969) 0(177.941,97.969) 0(177.941,167.969)
  oval 3.2x3.8 hole 2.2 slot 2.8 at 45 deg rot 135: 0(101.541,135.069) 0(135.341,168.869)
  oval 3.2x3.8 hole 2.2 slot 2.8 at 135 deg rot 45: 0(101.541,168.869) 0(135.341,135.069)

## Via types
v1: diameter 0.406, hole 0.203, GND02 to PWR13, 466 vias
v2: diameter 0.279, hole 0.127, Top Layer to GND02, tented top, 373 vias
v3: diameter 0.406, hole 0.203, Top Layer to Bottom Layer, 324 vias
v4: diameter 0.279, hole 0.127, PWR13 to Bottom Layer, 207 vias
v5: diameter 0.279, hole 0.127, Top Layer to ART03, tented top, 41 vias
v6: diameter 0.279, hole 0.127, Top Layer to ART03, 40 vias
v7: diameter 0.279, hole 0.127, PWR13 to Bottom Layer, tented bottom, 39 vias
v8: diameter 0.279, hole 0.127, ART12 to Bottom Layer, 30 vias
v9: diameter 0.279, hole 0.127, Top Layer to GND02, 20 vias
v10: diameter 0.406, hole 0.203, Top Layer to Bottom Layer, tented both sides, 16 vias
v11: diameter 0.406, hole 0.203, ART03 to ART12, 11 vias
v12: diameter 0.406, hole 0.203, Top Layer to Bottom Layer, tented top, 9 vias

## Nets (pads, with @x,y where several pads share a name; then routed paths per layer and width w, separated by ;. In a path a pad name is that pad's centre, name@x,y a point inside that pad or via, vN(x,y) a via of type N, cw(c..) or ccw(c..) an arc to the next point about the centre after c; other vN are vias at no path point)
ADDR3-A0: RR4.7 U1.N2 U6.N3 U8.N3 | length 30.7
  Top Layer w0.114: v2(111.265,158.965) U1.N2@111.665,158.565 ; U8.N3@117.9,164.135 117.9,164.421 117.602,164.719 117.602,165.583 117.399,165.786 117.399,166.065 117.526,166.192 v5(117.907,166.192) ; v6(123.325,169.041) RR4.7@123.96,169.041
  ART03 w0.102: v5(117.907,166.192) 117.907,166.446 118.7,167.239 v1(118.7,167.335)
  GND02 w0.102: v5(117.907,166.192) 117.907,166.776 118.288,167.157 118.288,167.64 118.643,167.996 121.539,167.996 122.022,168.478 122.352,168.478 122.915,169.041 v6(123.325,169.041)
  GND02 w0.109: v1(110.865,158.565) v2(111.265,158.965)
  ART08 w0.119: v1(110.865,158.565) 109.982,159.448 109.982,160.579 110.211,160.807 113.436,160.807 113.919,161.29 113.919,165.202 115.354,166.636 118.376,166.636 118.7,166.96 v1(118.7,167.335)
  PWR13 w0.114: v7(118.3,167.735) v1(118.7,167.335)
  Bottom Layer w0.114: U6.N3@117.9,167.335 v7(118.3,167.735)
ADDR3-A1: RR7.6 U1.K2 U6.P7 U8.P7 | length 28.7
  Top Layer w0.114: v1(114.065,158.565) v2(114.465,158.965) ; U8.P7@118.7,167.335 118.7,166.923 119.151,166.472 119.151,166.319 119.022,166.19 118.745,166.19 v5(118.751,166.184) ; v6(123.325,167.255) RR7.6@123.96,167.255
  ART03 w0.102: v5(118.751,166.184) 118.751,165.913 119.068,165.596 119.068,164.566 v1(119.5,164.135)
  ART10 w0.109: v1(114.065,158.565) 114.605,159.105 114.605,160.274 116.688,162.357 116.688,163.17 117.526,164.008 117.526,164.567 118.313,165.354 118.313,166.573 118.458,166.718 118.677,166.718 118.847,166.548 118.847,165.633 118.974,165.506 119.202,165.506 119.329,165.633 119.329,166.7 119.507,166.878 119.71,166.878 119.888,166.7 119.888,164.523 v1(119.5,164.135)
  GND02 w0.102: v5(118.751,166.184) 119.521,166.954 121.26,166.954 121.92,167.615 122.965,167.615 v6(123.325,167.255)
  GND02 w0.109: v1(114.065,158.565) v2(114.465,158.965)
  PWR13 w0.114: v7(119.1,163.735) v1(119.5,164.135)
  Bottom Layer w0.114: U6.P7@118.7,164.135 v7(119.1,163.735)
ADDR3-A2: RR7.7 U1.M3 U6.P3 U8.P3 | length 28.8
  Top Layer w0.114: v2(112.065,158.165) v1(112.465,157.765) ; U8.P3@118.7,164.135 118.7,164.377 119.05,164.727 119.05,165.17 v5(118.751,165.469) ; v6(123.325,166.755) RR7.7@123.96,166.755
  ART03 w0.102: v5(118.751,165.469) 118.459,165.761 118.459,166.363 118.6,166.504 118.879,166.504 119.5,167.125 v1(119.5,167.335)
  ART10 w0.109: v1(112.465,157.765) 112.979,158.279 112.979,159.156 115.9,162.077 115.9,163.093 116.713,163.906 116.713,164.338 117.932,165.557 117.932,166.726 118.288,167.081 118.288,168.097 118.669,168.478 120.167,168.478 120.345,168.3 120.345,167.996 120.167,167.818 119.983,167.818 v1(119.5,167.335)
  GND02 w0.102: v5(118.751,165.469) 119.151,165.869 119.151,166.116 119.761,166.726 121.971,166.726 122,166.755 v6(123.325,166.755)
  GND02 w0.109: v2(112.065,158.165) v1(112.465,157.765)
  PWR13 w0.114: v7(119.1,167.735) v1(119.5,167.335)
  Bottom Layer w0.114: U6.P3@118.7,167.335 v7(119.1,167.735)
ADDR3-A3: RR6.5 U1.K3 U6.N2 U8.N2 | length 31.5
  Top Layer w0.114: U1.K3@114.065,157.765 v2(114.465,158.165) ; v5(117.29,164.834) 117.29,164.599 117.5,164.389 117.5,163.735 U8.N2@117.9,163.335
  ART03 w0.102: v5(117.29,164.834) 117.616,165.159 117.616,166.07 117.615,166.071 117.615,166.51 118.306,167.201 118.306,168.542 v1(118.7,168.935)
  ART05 w0.109: v1(118.7,168.935) 118.7,168.625 119.228,168.097 123.774,168.097 v11(124.046,168.369)
  ART12 w0.102: v1(114.865,158.565) 114.44,158.14 113.843,158.14 113.563,158.42 113.563,160.745 114.75,161.932 114.75,164.707 115.068,165.024 116.129,165.024 116.719,165.614 116.719,167.468 116.967,167.716 117.348,167.716 117.678,168.046 118.288,168.046 118.7,168.459 v1(118.7,168.935) ; v8(123.325,168.521) 123.893,168.521 v11(124.046,168.369)
  GND02 w0.102: v2(114.465,158.165) v1(114.865,158.565)
  PWR13 w0.114: v7(118.3,168.535) v1(118.7,168.935)
  Bottom Layer w0.114: U6.N2@117.9,168.135 v7(118.3,168.535) ; v8(123.325,168.521) RR6.5@123.96,168.521
ADDR3-A4: RR7.8 U1.M4 U6.P8 U8.P8 | length 29.3
  Top Layer w0.114: v2(112.065,157.365) v1(112.465,156.965) ; U8.P8@118.7,168.135 119.132,167.703 119.132,167.024 119.703,166.453 v5(119.703,166.184) ; v6(123.325,166.235) RR7.8@123.96,166.235
  ART03 w0.102: v1(119.5,162.535) 119.894,162.929 119.894,164.453 120.021,164.58 120.021,165.78 119.703,166.097 v5(119.703,166.184)
  GND02 w0.102: v5(119.703,166.184) 119.996,166.476 123.084,166.476 v6(123.325,166.235)
  GND02 w0.109: v2(112.065,157.365) v1(112.465,156.965)
  ART07 w0.119: v1(112.465,156.965) 112.693,156.965 113.081,157.353 113.767,157.353 114.554,156.566 119.056,156.566 119.234,156.744 119.234,157.157 119.438,157.36 119.856,157.36 120.084,157.589 120.084,157.988 119.907,158.166 119.405,158.166 119.278,158.293 119.278,158.801 119.456,158.979 119.932,158.979 120.084,159.131 120.084,159.607 120.904,160.426 120.904,160.96 120.625,161.239 120.04,161.239 119.913,161.366 119.913,162.122 v1(119.5,162.535)
  PWR13 w0.114: v7(119.1,162.935) v1(119.5,162.535)
  Bottom Layer w0.114: U6.P8@118.7,163.335 v7(119.1,162.935)
ADDR3-A5: RR1.8 U1.L1 U6.P2 U8.P2 | length 31.8
  Top Layer w0.114: v2(112.865,159.765) U1.L1@113.265,159.365 ; U8.P2@118.7,163.335 118.306,163.729 118.306,164.406 v5(118.751,164.851) ; v6(123.325,161.663) RR1.8@123.96,161.663
  ART03 w0.102: v5(118.751,164.851) 118.751,165.06 118.635,165.176 118.63,165.176 118.255,165.552 118.255,166.447 118.585,166.776 118.796,166.776 119.101,167.081 119.101,168.536 v1(119.5,168.935)
  GND02 w0.102: v5(118.751,164.851) 119.101,164.501 119.101,163.932 119.659,163.373 121.056,163.373 122.766,161.663 v6(123.325,161.663)
  GND02 w0.109: v1(112.465,159.365) v2(112.865,159.765)
  ART07 w0.119: v1(112.465,159.365) 113.228,159.365 113.64,158.953 116.002,158.953 116.891,159.842 116.891,160.858 117.5,161.468 117.5,165.354 118.44,166.294 119.101,166.294 119.888,167.081 119.888,168.547 v1(119.5,168.935)
  PWR13 w0.114: v7(119.1,168.535) v1(119.5,168.935)
  Bottom Layer w0.114: U6.P2@118.7,168.135 v7(119.1,168.535)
